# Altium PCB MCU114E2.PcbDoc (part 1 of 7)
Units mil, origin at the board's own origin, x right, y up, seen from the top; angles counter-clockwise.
Board outline 4153.94 x 2313.28 mil, 8 copper layers (Top Layer, GND 2, Signal Layer 3, Power 4, Power 5, Signal Layer 6, GND 7, Bottom), stack 61.2 mil thick; 444 components, 418 nets, 1811 pads, 981 vias.
Unrouted connection lines stored in the file: 3.
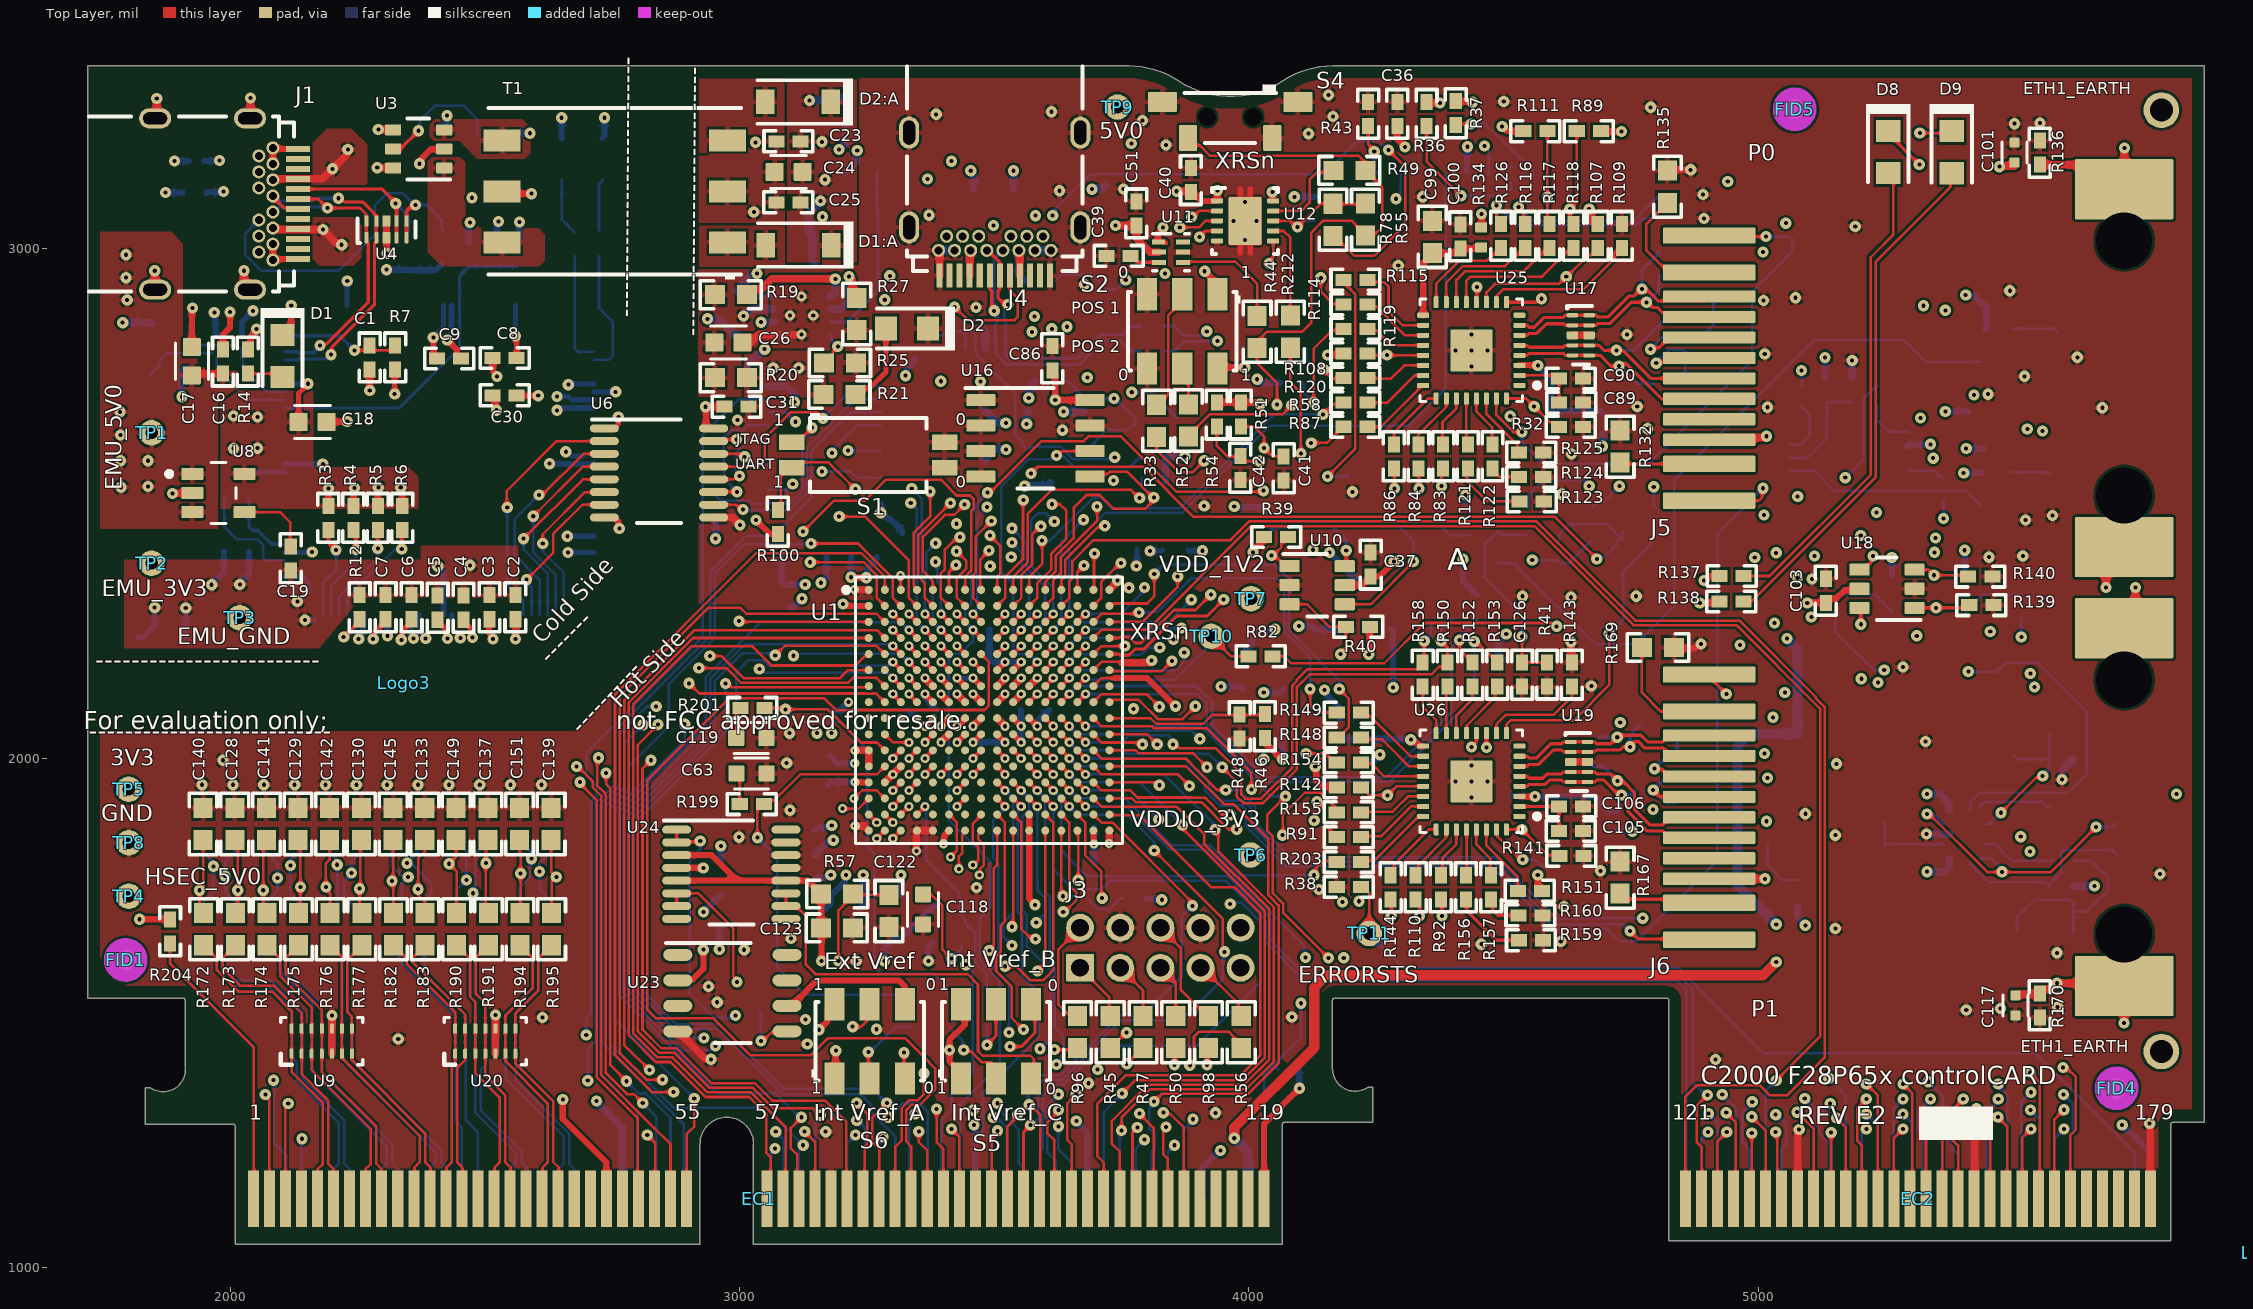
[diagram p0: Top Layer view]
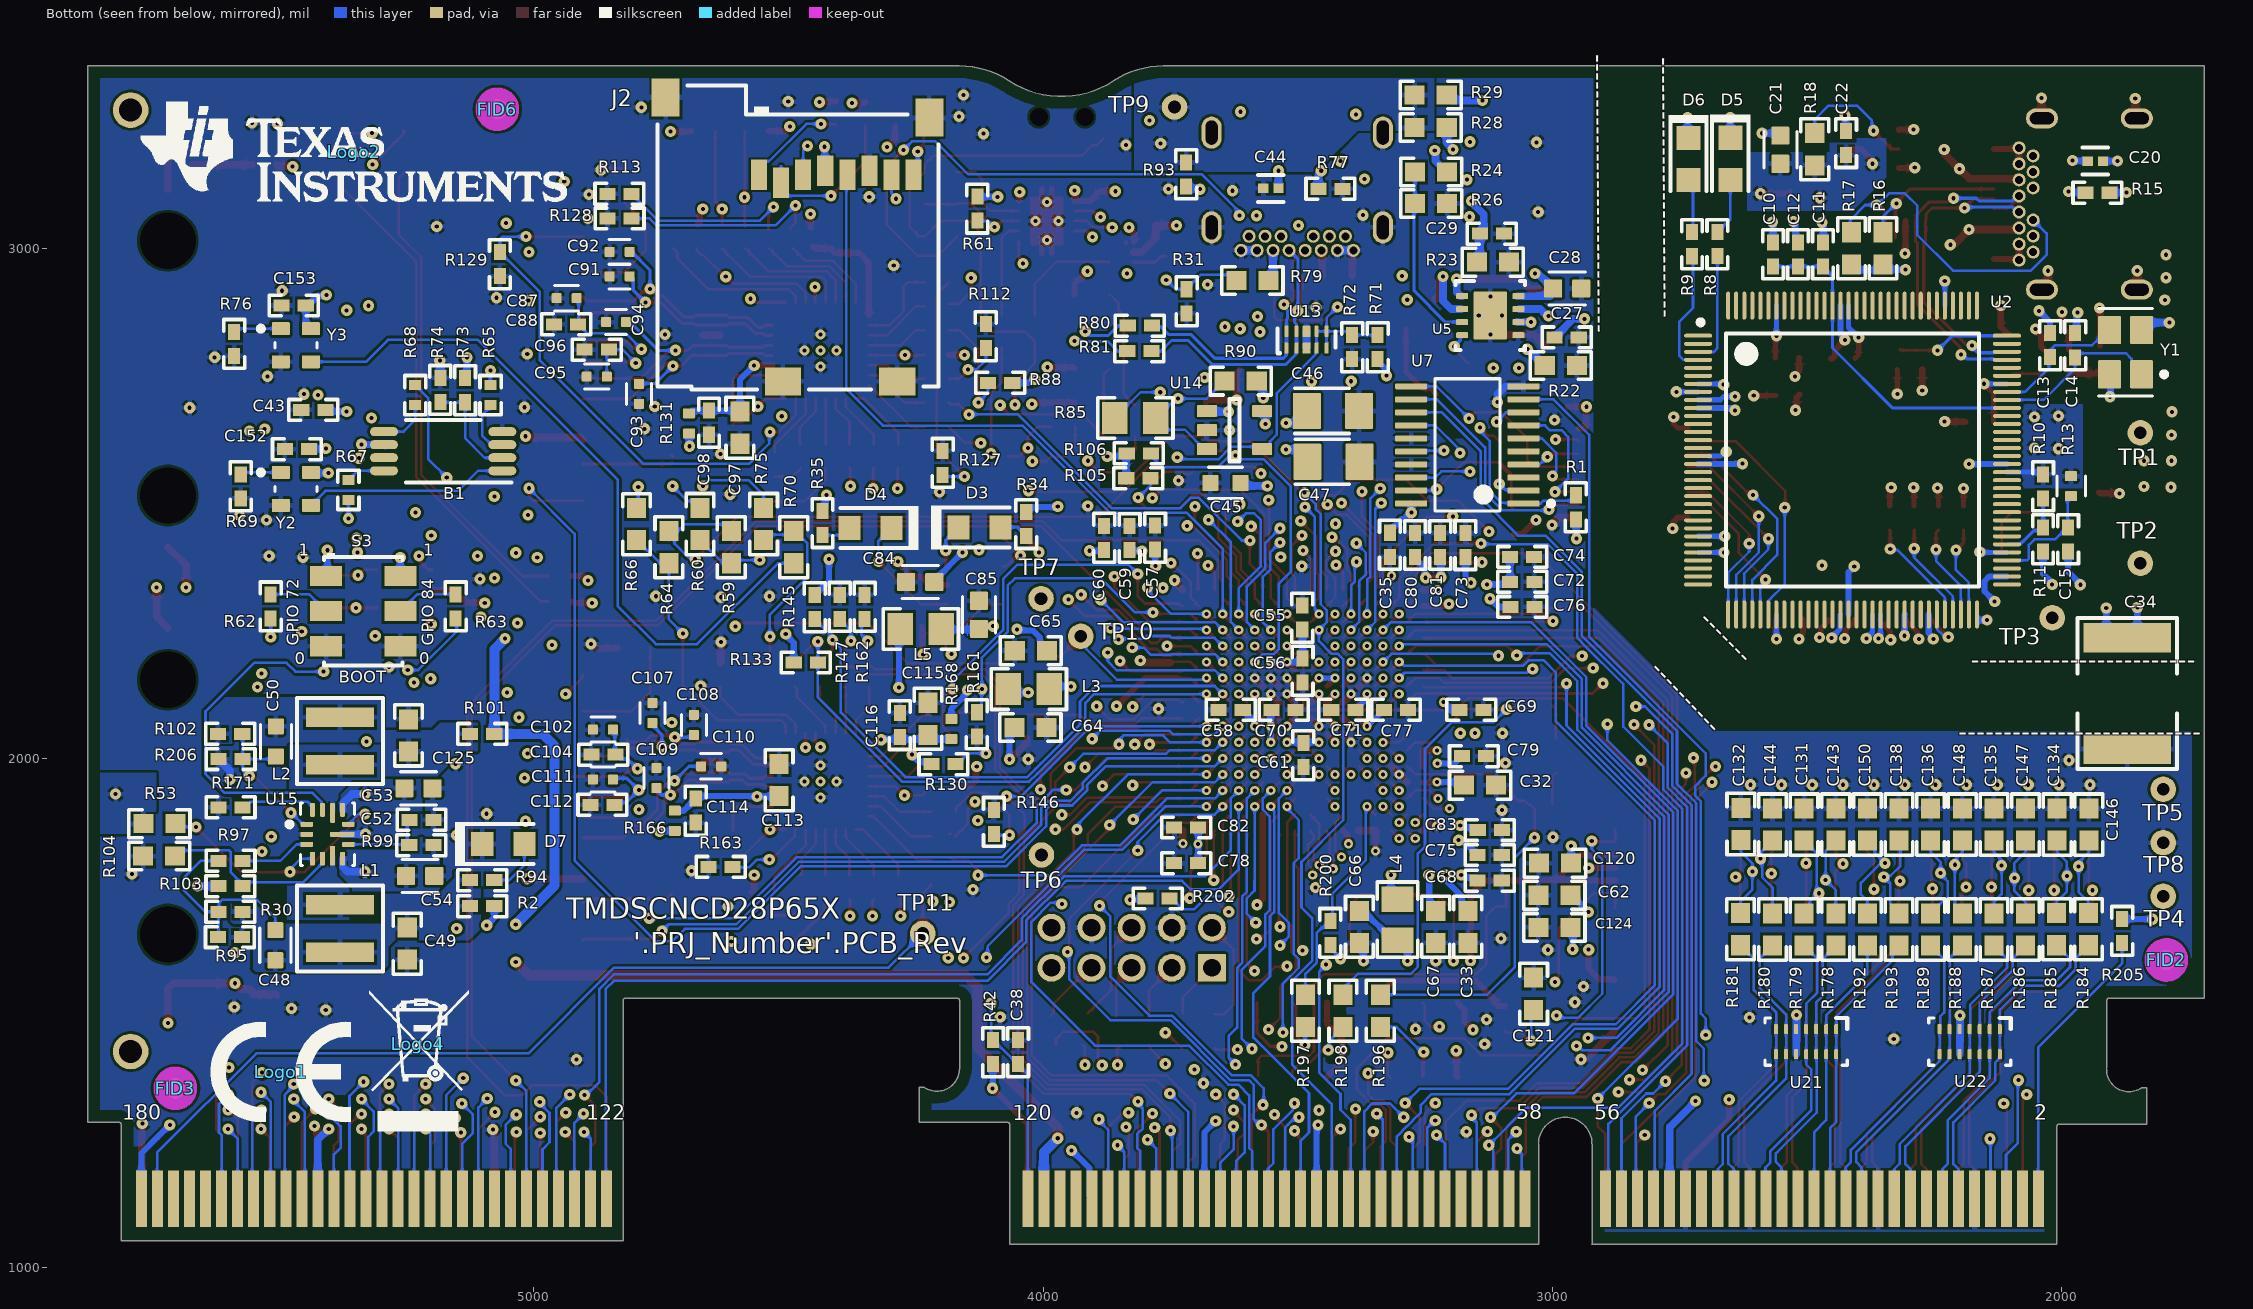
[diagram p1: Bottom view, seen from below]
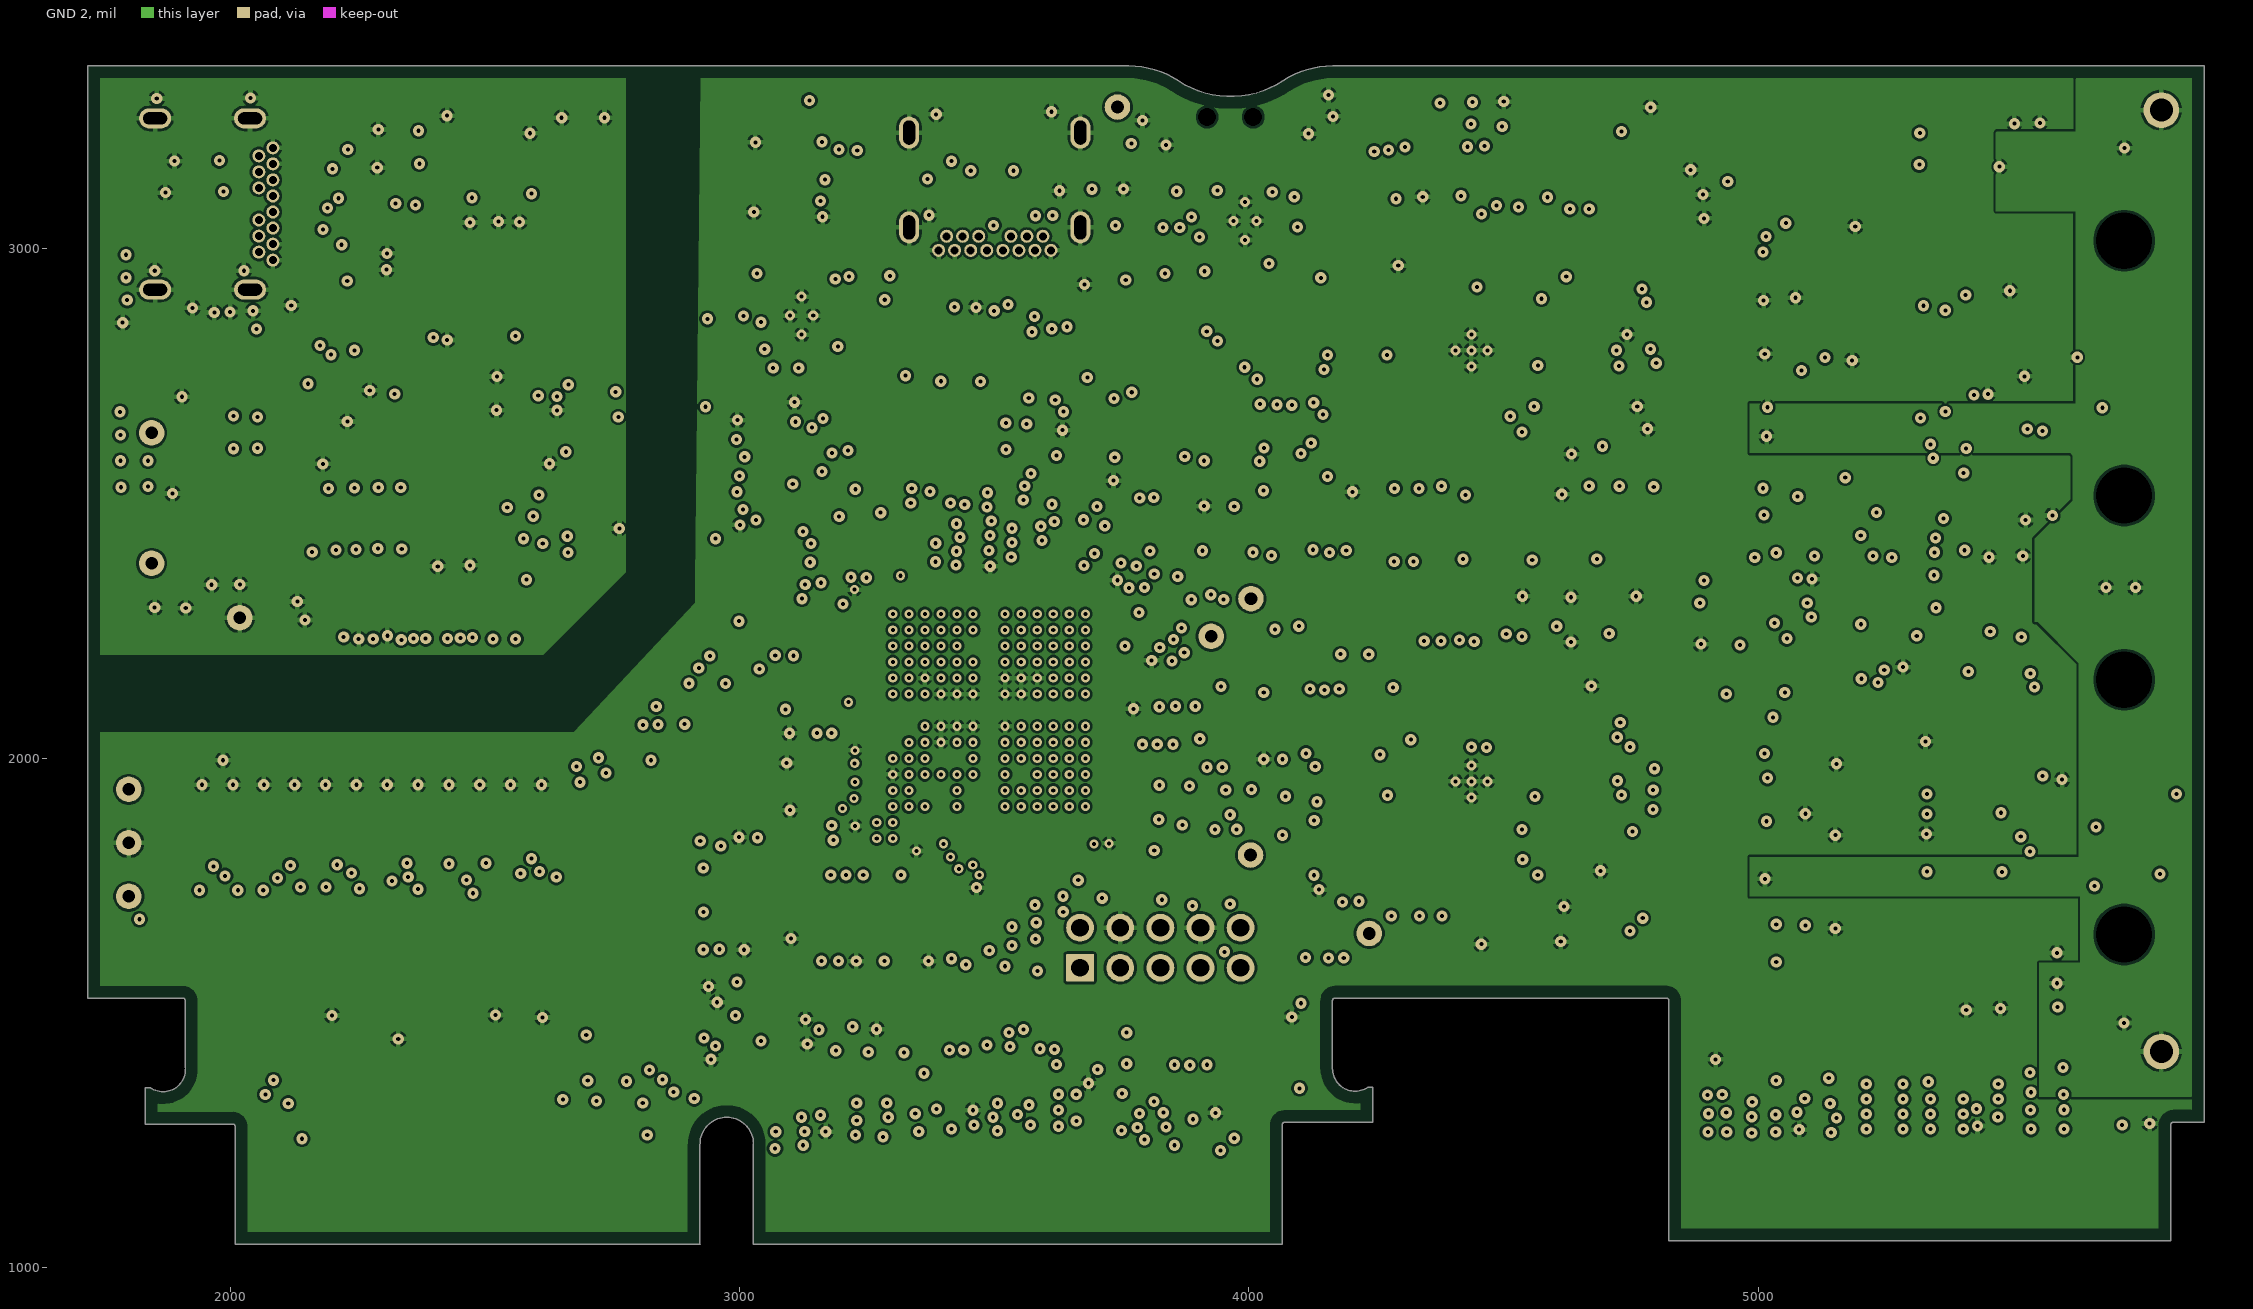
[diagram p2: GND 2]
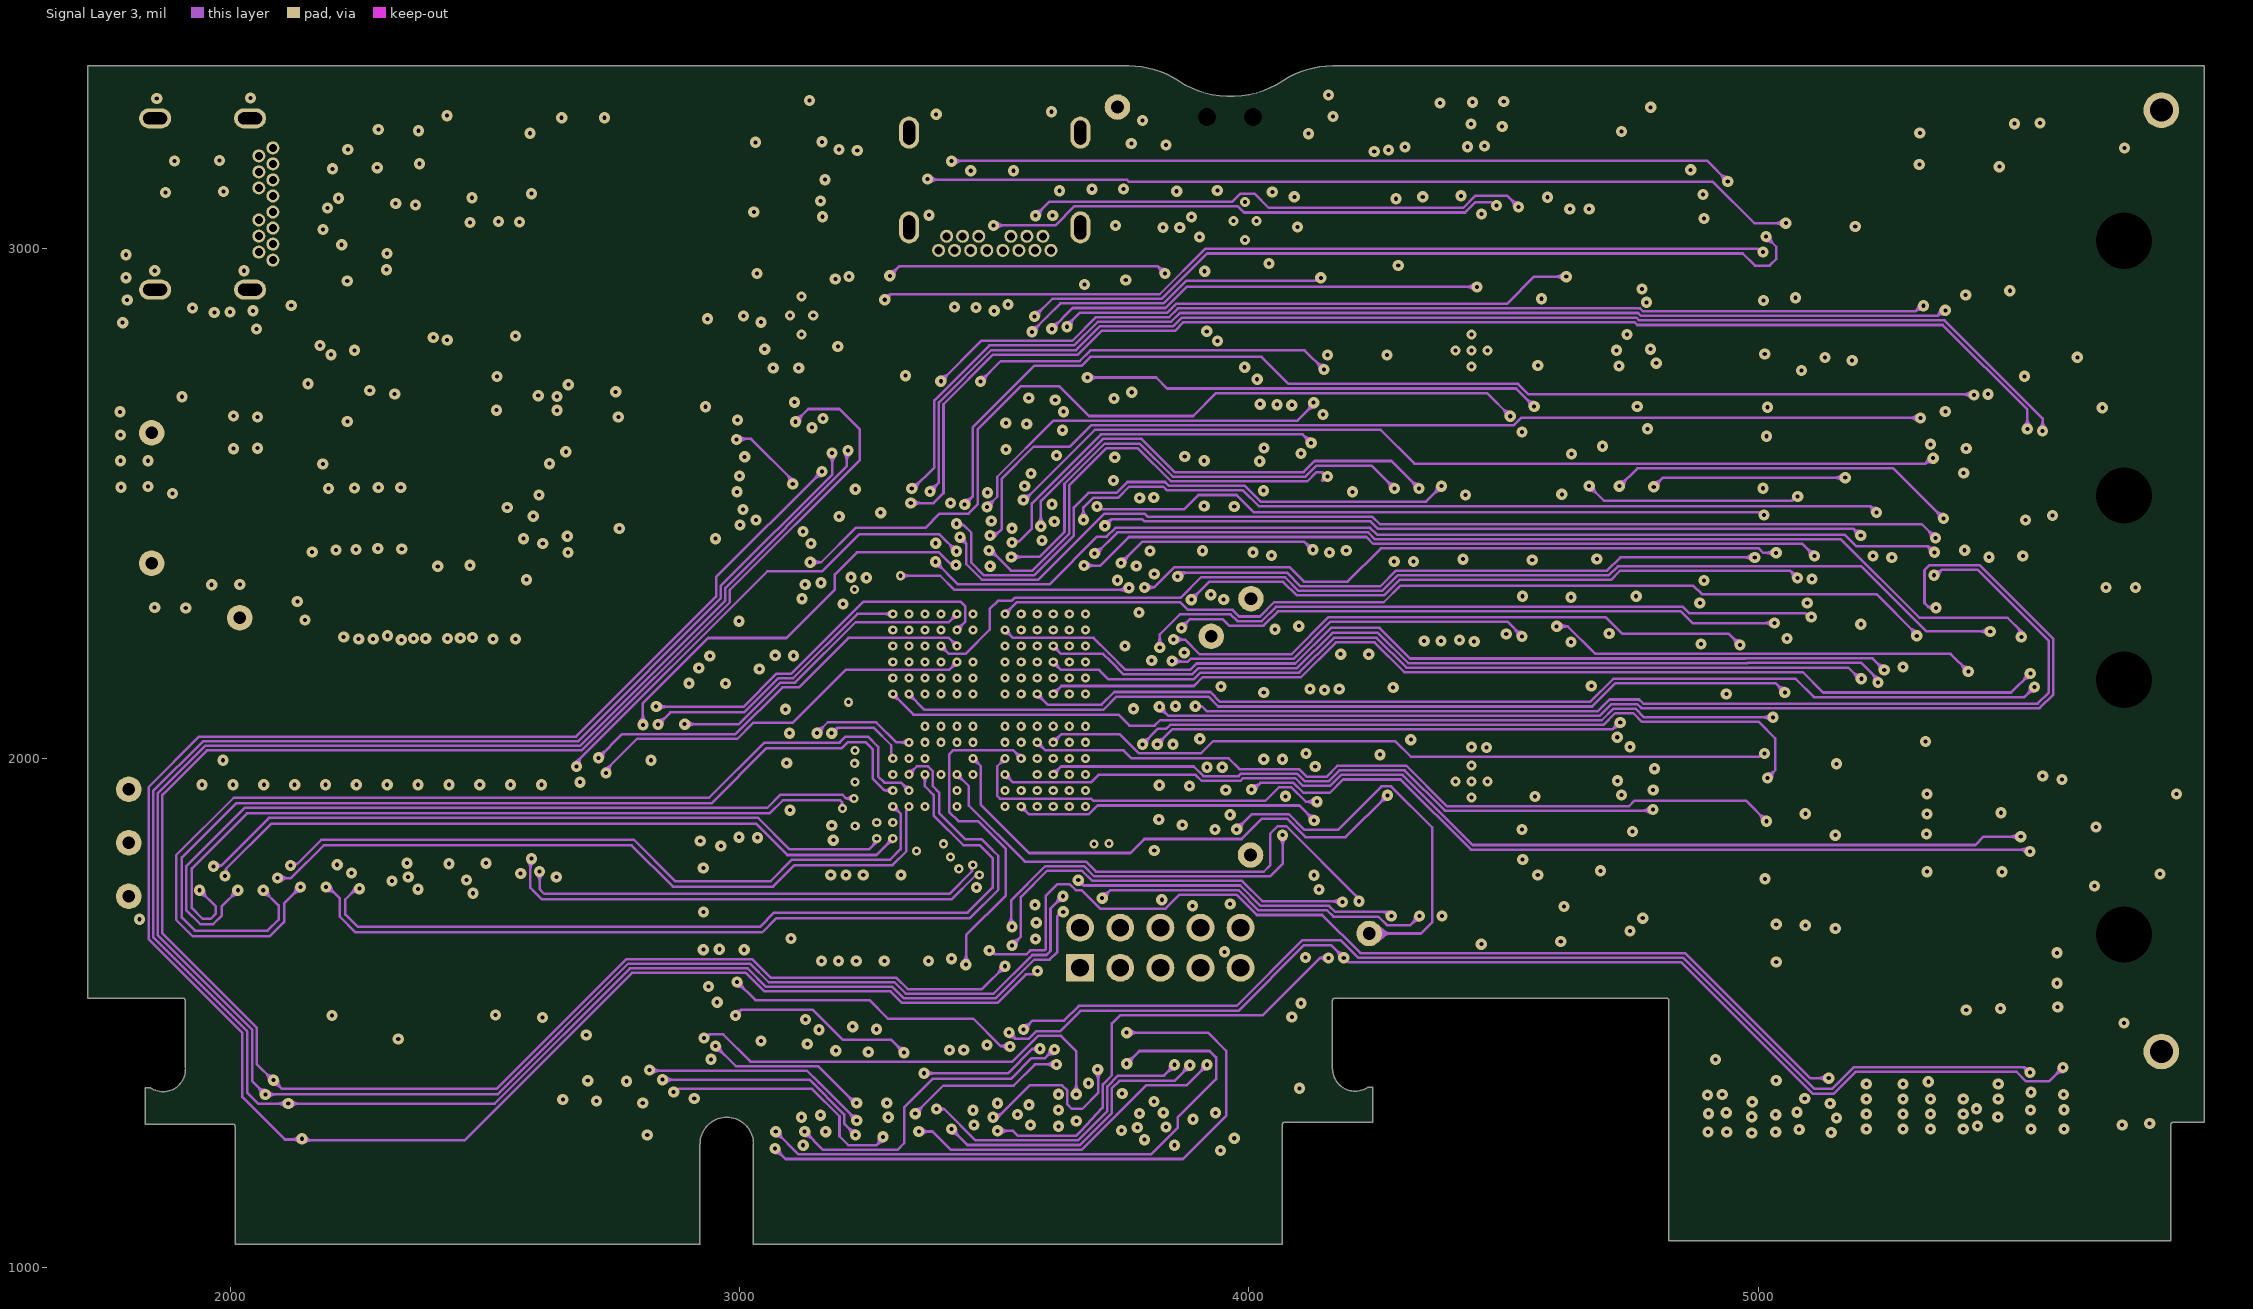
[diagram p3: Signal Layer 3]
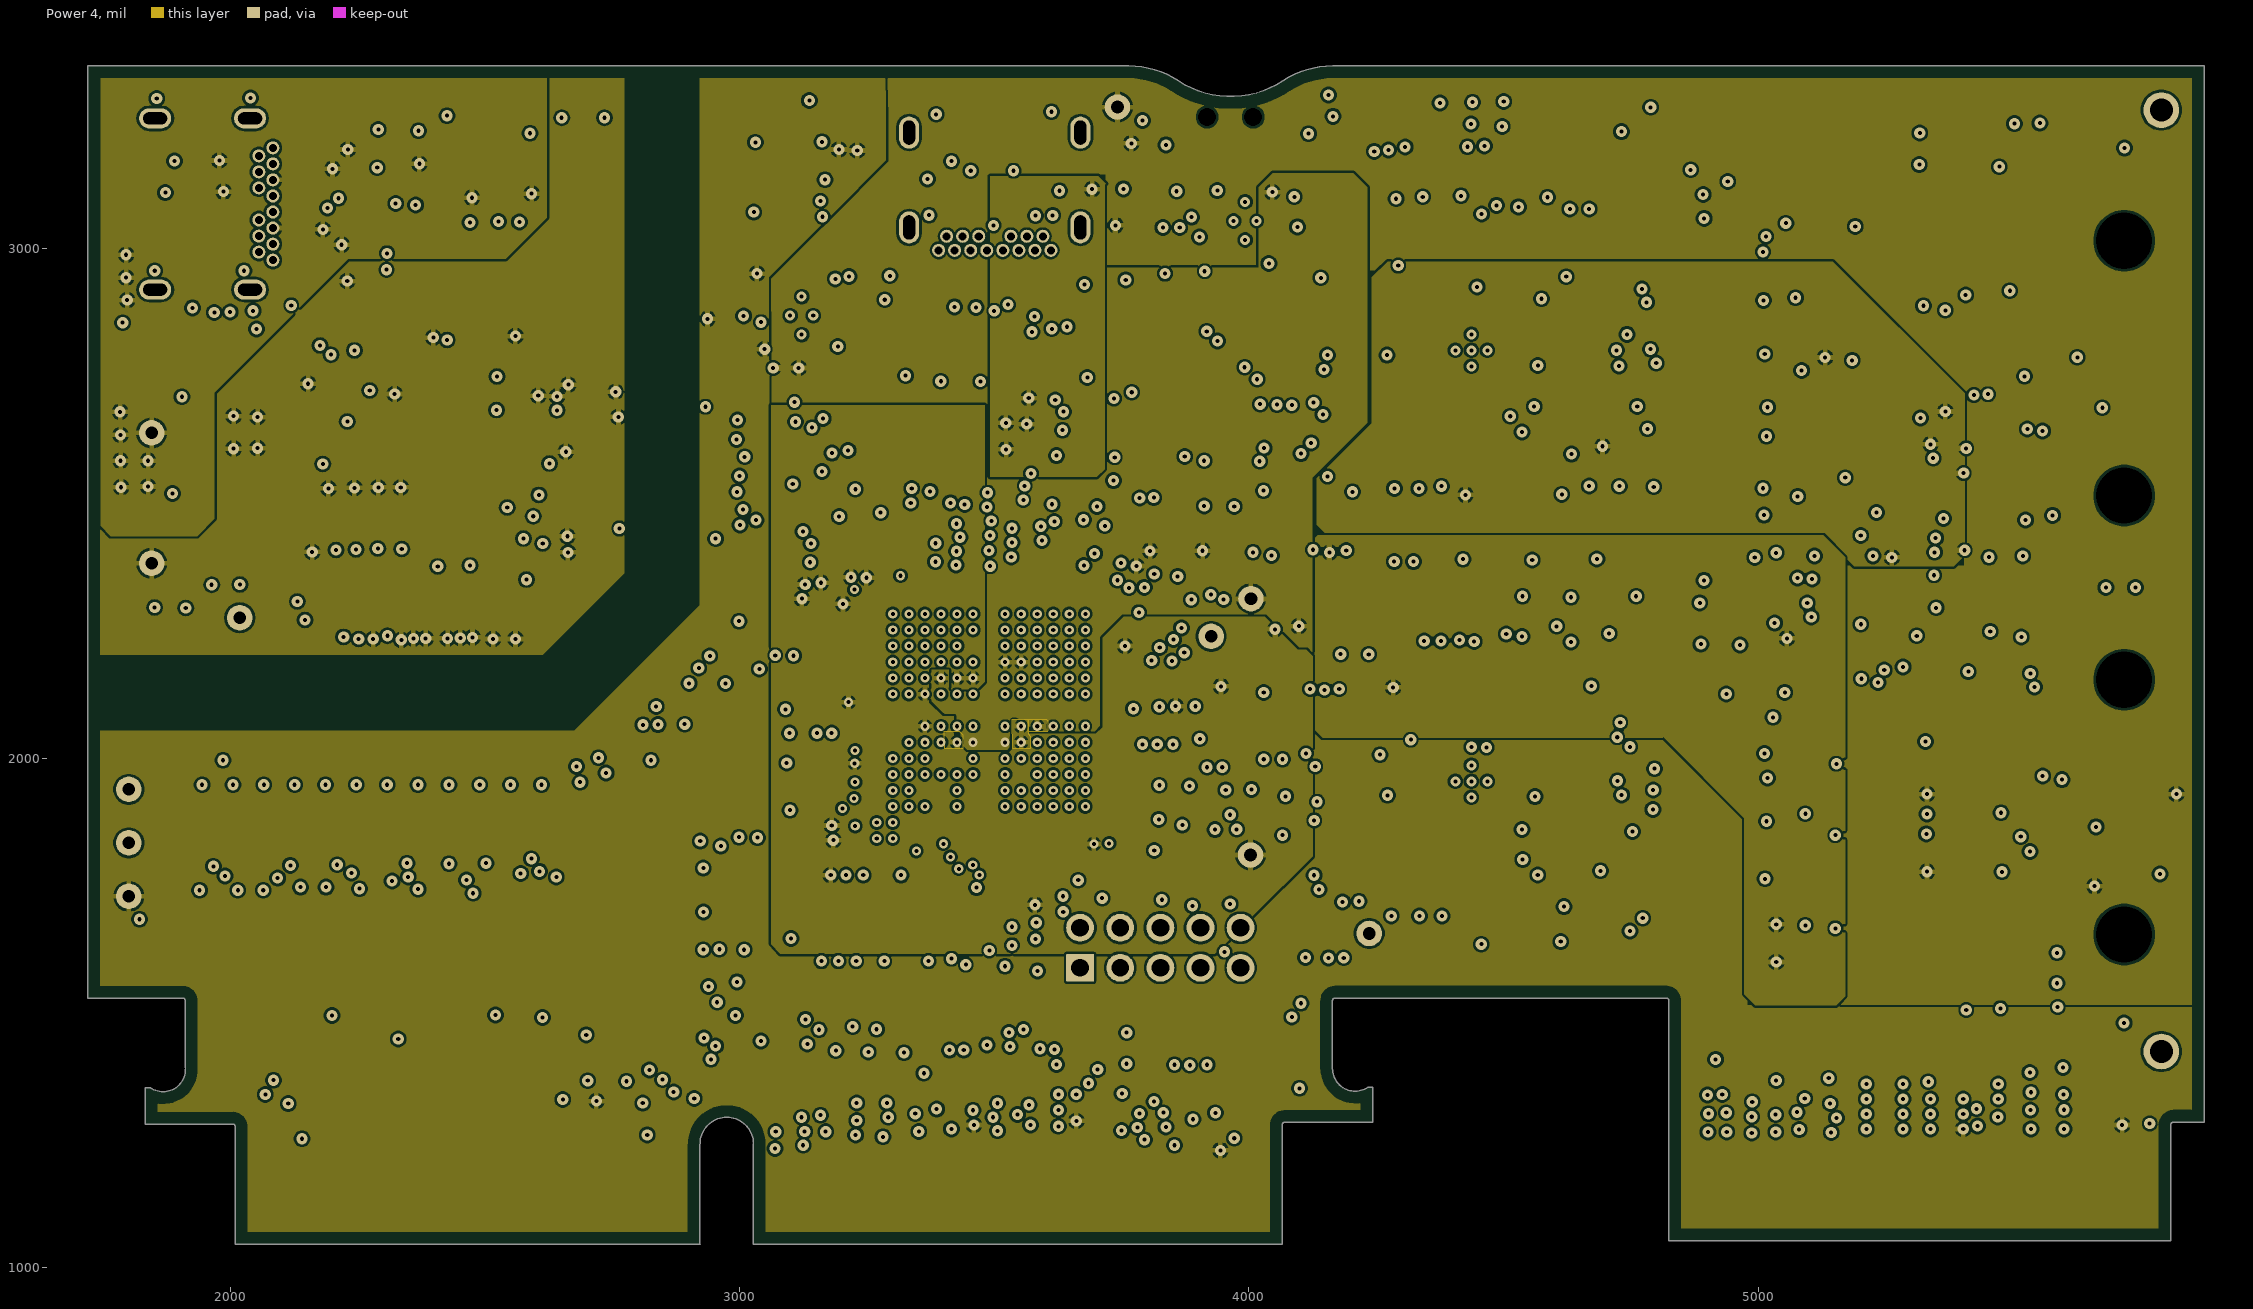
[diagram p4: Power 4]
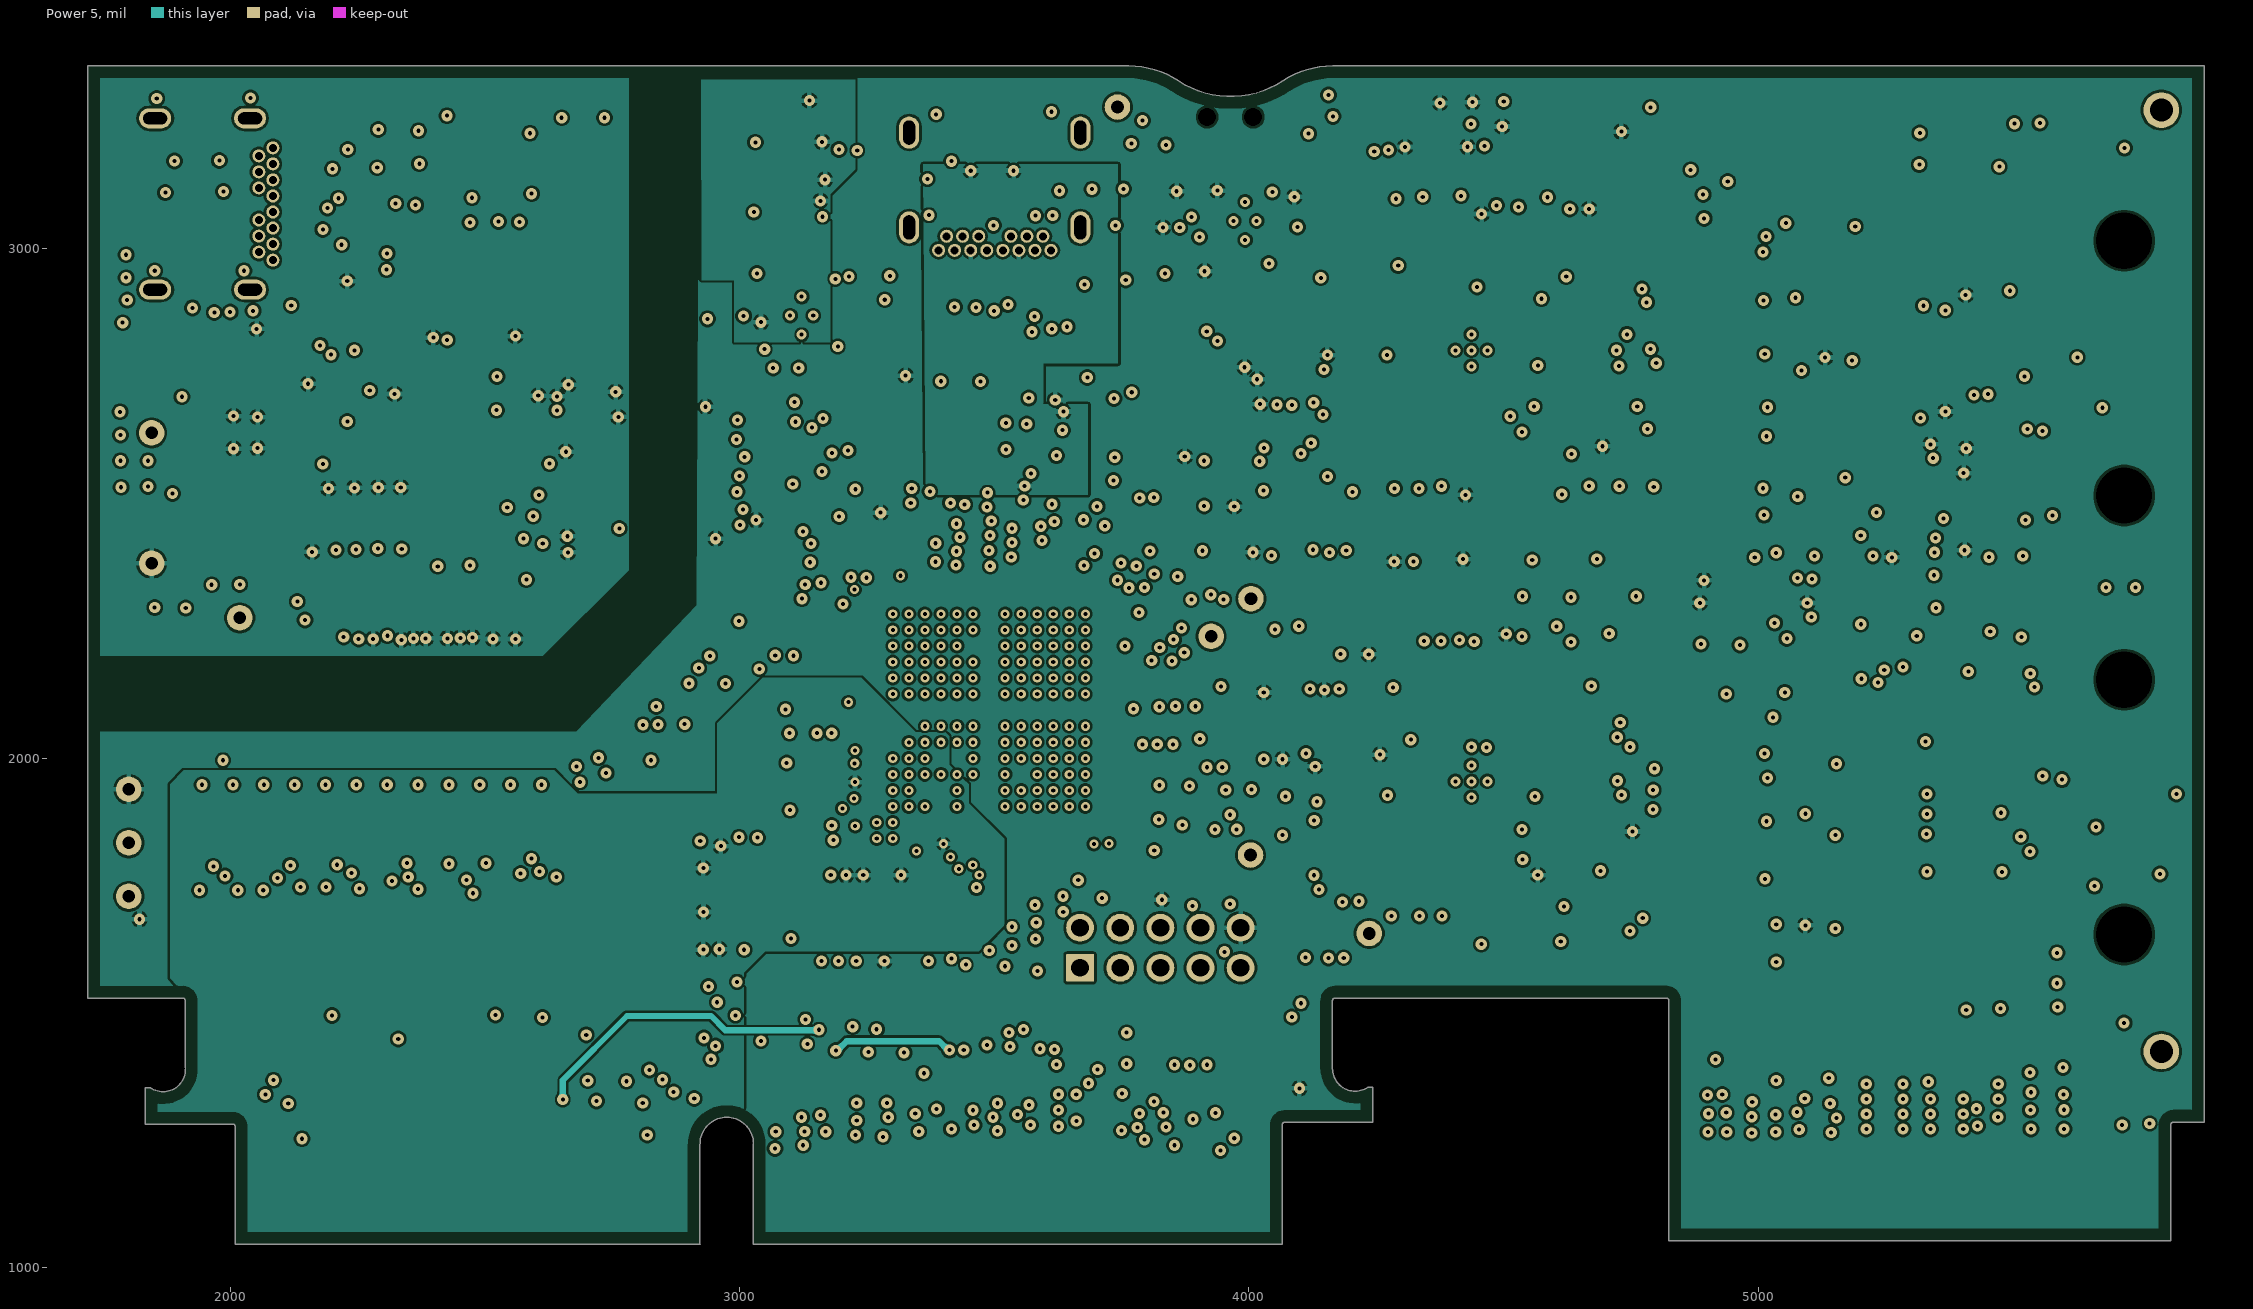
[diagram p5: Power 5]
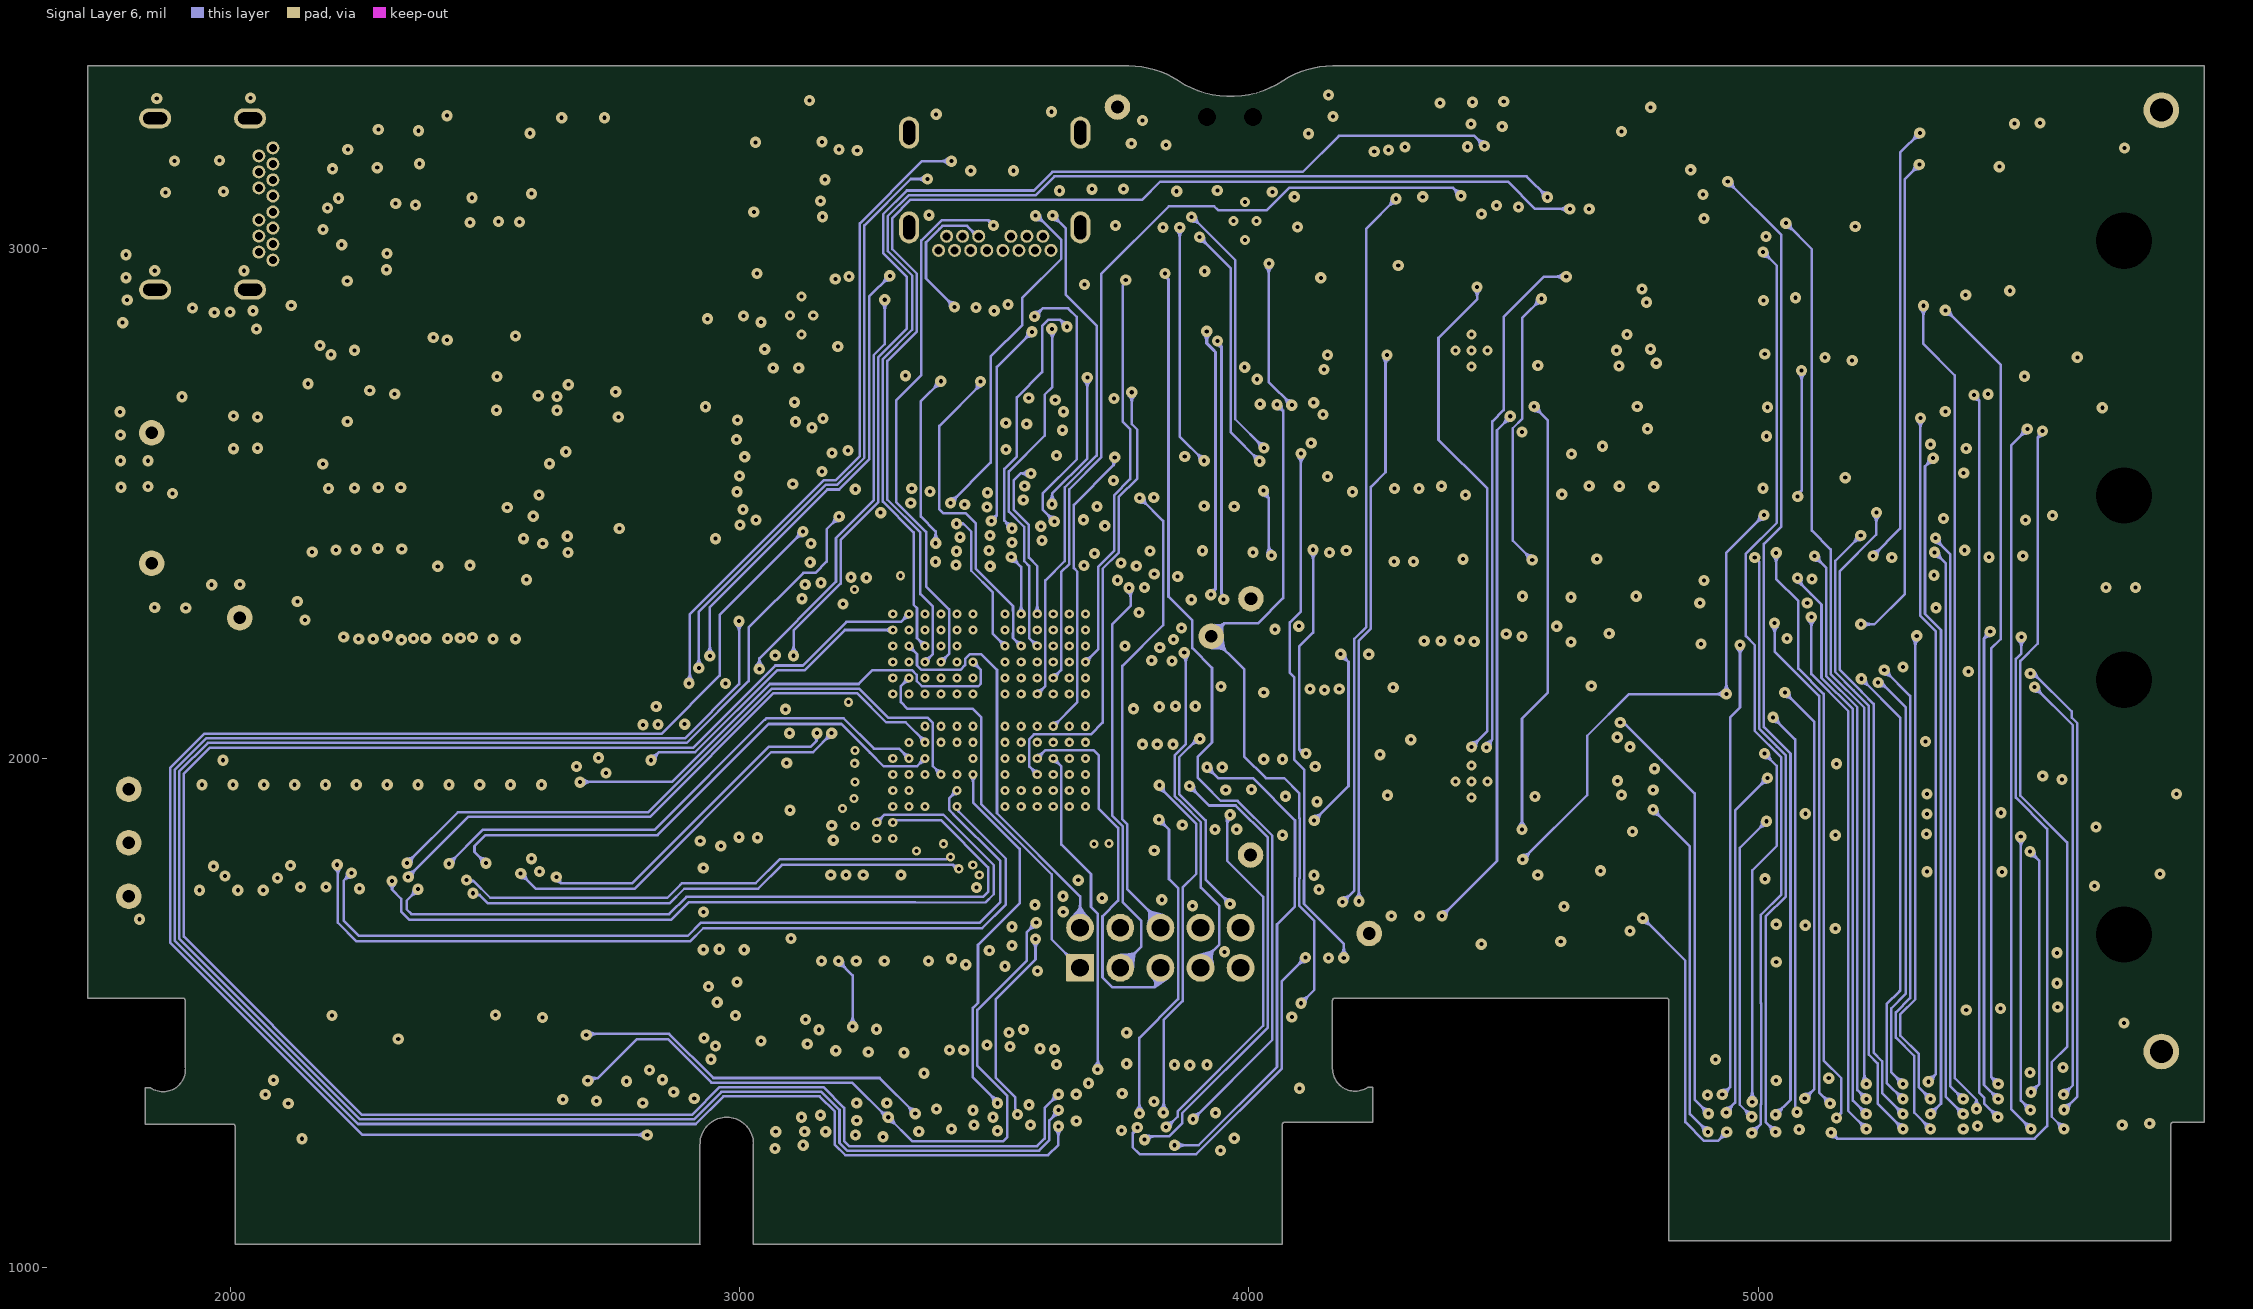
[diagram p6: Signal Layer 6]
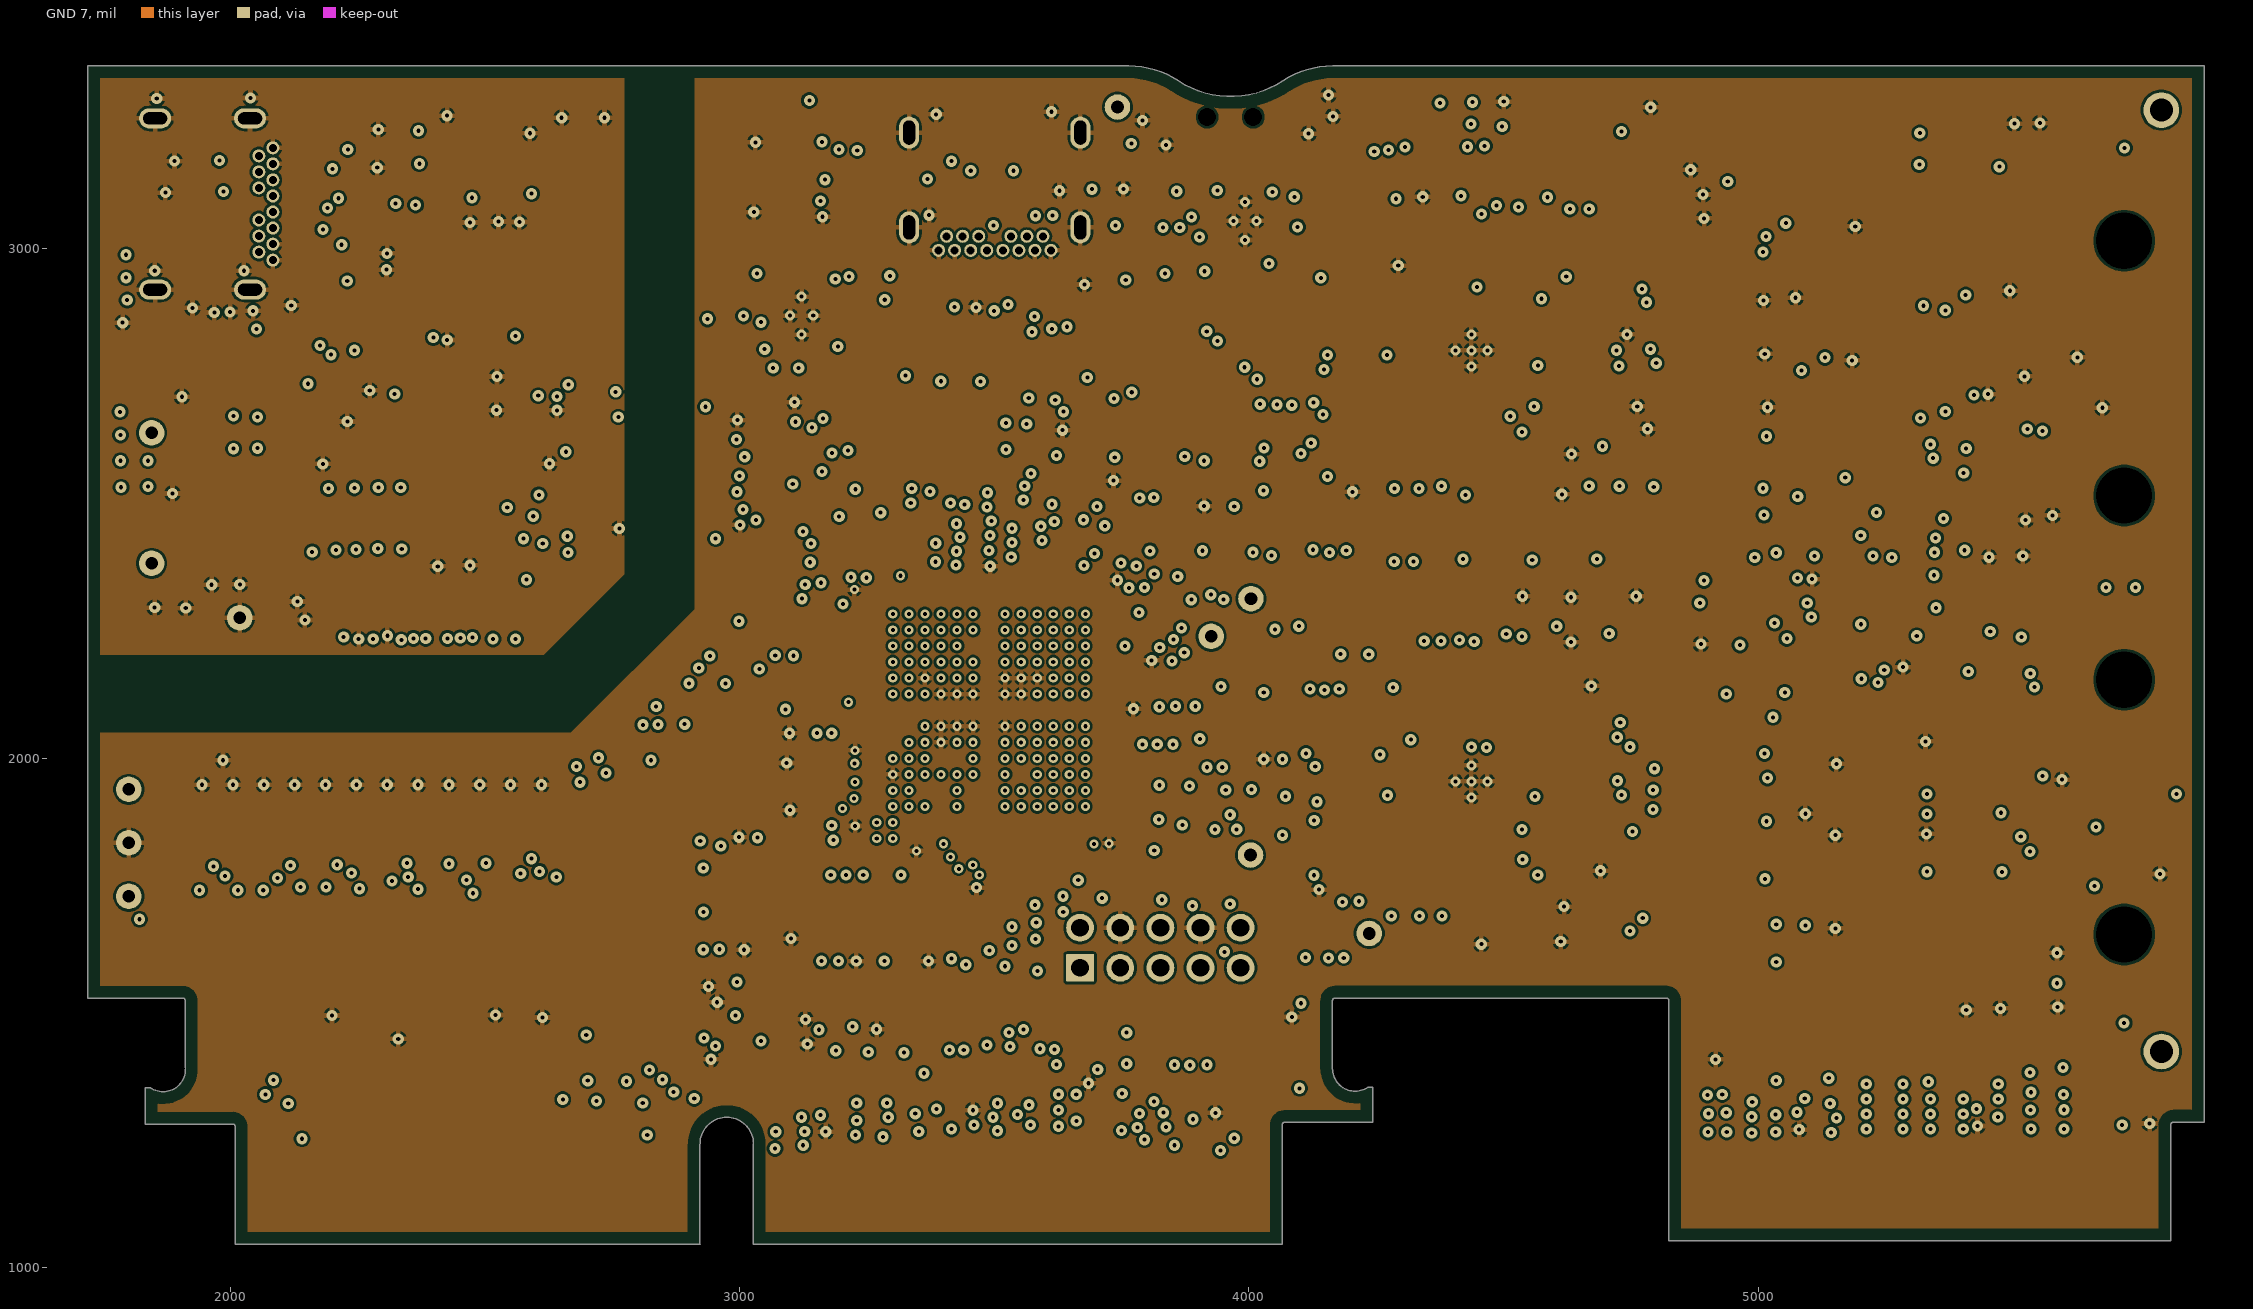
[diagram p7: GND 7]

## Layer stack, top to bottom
Top Solder: solder mask 0.5, Solder Resist, Dk 3.6
Top Layer: signal copper 1.4
Dielectric 1: prepreg 5, FR-4, Dk 3.7
GND 2: signal copper 1.4
Dielectric 2: core 10, FR-4, Dk 3.7
Signal Layer 3: signal copper 1.4
Dielectric 3: prepreg 5, FR-4, Dk 3.7
Power 4: signal copper 1.4
Dielectric 4: core 10, FR-4, Dk 3.7
Power 5: signal copper 1.4
Dielectric 5: prepreg 5, FR-4, Dk 3.7
Signal Layer 6: signal copper 1.4
Dielectric 6: core 10, FR-4, Dk 3.7
GND 7: signal copper 1.4
Dielectric 7: prepreg 5, FR-4, Dk 3.7
Bottom: signal copper 1.4
Bottom Solder: solder mask 0.5, Solder Resist, Dk 3.6

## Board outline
1833.82,1282.02 2005,1282.02 cw(c2005,1277) 2010.02,1277 2010.02,1045.98 2010.84,1046.05 2922.46,1046.05 2922.25,1047.48 2922.25,1241.96 2922.35,1242.97 cw(c2974.85,1242.55) 3027.35,1242.97 3027.35,1242.93 3027.35,1045.77 3027.41,1045.71 4065.16,1045.77 4065.09,1046.6 4065.09,1276.93 4065.38,1278.6 cw(c4070.11,1280.27) 4070.11,1285.28 4242.79,1285.28 4242.79,1354.25 4233.43,1354.25 cw(c4208.3,1390.39) 4164.35,1387.95 4163.79,1390.27 4163.79,1524.27 cw(c4168.8,1524.27) 4168.8,1529.28 4819.11,1529.28 cw(c4819.11,1524.27) 4824.13,1524.27 4824.13,1053.28 5809.38,1053.28 5809.38,1280.37 cw(c5814.39,1280.37) 5814.39,1285.38 5874.79,1285.38 5874.79,3358.99 4167,3358.99 4164,3358.99 ccw(c4164,3182.33) 4066.76,3329.81 cw(c3964,3485.67) 3861.24,3329.81 ccw(c3764,3182.33) 3764,3358.98 3763.85,3358.99 1720.85,3358.99 1720.85,1529.28 1906.8,1529.28 cw(c1906.8,1524.27) 1911.82,1524.27 1911.82,1393.48 1912.37,1389.36 cw(c1868.35,1389.36) 1843.18,1353.25 1833.82,1353.25

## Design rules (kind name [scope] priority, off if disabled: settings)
AcuteAngle [All] p1: minimum=4.50000000000000E+0001 checktracksonly=TRUE
AssemblyTestPointUsage [All] p1: valid=2
BoardOutlineClearance "Edge exception" [OnCopper and Not InComponentClass('Logo') and not InComponentClass('FiducialMark') and not InRegion(1000,500,4000,800) and not InPoly and ((Name = 'EC2') or (Name = 'EC1'))] p1: gap=0 ignorepadtopadclearanceinfootprint=FALSE
BoardOutlineClearance [All] p2: gap=24 ignorepadtopadclearanceinfootprint=FALSE except(0: Text-OutlineEdge; 15: Arc-OutlineEdge Track-OutlineEdge SMDPad-OutlineEdge Fill-OutlineEdge)
BoardOutlineClearance BoardOutlineClearance_MountingHoles [OnCopper and InComponentClass('Mounting Holes')] p3: gap=40 ignorepadtopadclearanceinfootprint=FALSE
BoardOutlineClearance BoardOutlineClearance_Poly [OnCopper and IsPoly] p4: gap=25 ignorepadtopadclearanceinfootprint=FALSE
Clearance "Clearance_RJ45 pad" [InComponent('J5') OR InComponent('J6')] p1: gap=5 ignorepadtopadclearanceinfootprint=TRUE except(0: SMDPad-THPad)
Clearance Clearance_Keepouts [((IsTrack Or IsArc) And Not InPoly) And IsFree and IsKeepOut vs ((IsTrack Or IsArc) And Not InPoly) And IsFree and IsKeepOut] p2: gap=5 ignorepadtopadclearanceinfootprint=FALSE
Clearance Clearance_Poly [InPolygon] p3: gap=5 ignorepadtopadclearanceinfootprint=FALSE
Clearance Clearance_FiducialMark [IsKeepOut and InComponentClass('FiducialMark') vs IsPad and InComponentClass('FiducialMark')] p4: gap=0 ignorepadtopadclearanceinfootprint=FALSE
Clearance [All] p5: gap=5 ignorepadtopadclearanceinfootprint=FALSE except(4: Arc-Arc Arc-Track Arc-Via Track-Track Track-Via)
ComponentClearance ComponentClearance_TI_LOGO [InComponentClass('Logo')] p1: gap=0 collisioncheckmode=3 verticalgap=0 showdistances=FALSE
ComponentClearance ComponentClearance_MountingHoles_FiducialMarks [InComponentClass('Mounting Holes') vs InComponentClass('FiducialMark')] p2: gap=10 collisioncheckmode=3 verticalgap=10 showdistances=FALSE
ComponentClearance ComponentClearance_Shunt [InComponentClass('Header') vs InComponentClass('Shunt')] p3: gap=0 collisioncheckmode=3 verticalgap=0 showdistances=FALSE
ComponentClearance ComponentClearance_Logo [InComponentClass('Logo')] p4: gap=10 collisioncheckmode=3 verticalgap=10 showdistances=FALSE
ComponentClearance ComponentClearance_ScrewToNut [(HasFootprint('NY PMS 440 0025 PH')) vs (HasFootprint('Keystone_1902C'))] p5: gap=5 collisioncheckmode=3 verticalgap=10 showdistances=FALSE
ComponentClearance ComponentClearance_MountingHoles [InComponentClass('Mounting Holes')] p6: gap=250 collisioncheckmode=3 verticalgap=100000 showdistances=FALSE
ComponentClearance ComponentClearance_SmallPassives [HasFootprint('0201*') or HasFootprint('0402*') or HasFootprint('0508') or HasFootprint('0603*') or HasFootprint('0612') or HasFootprint('0805*') or HasFootprint('0815*') or HasFootprint('0830*') or HasFootprint('1206*') or HasFootprint('1210*') or HasFootprint('1808*') or HasFootprint('1812*') or HasFootprint('1825*') or HasFootprint('2010*') or HasFootprint('2220*') or HasFootprint('2225*') or HasFootprint('2512*') or HasFootprint('2728*') or HasFootprint('3518*') vs HasFootprint('0201*') or HasFootprint('0402*') or HasFootprint('0508') or HasFootprint('0603*') or HasFootprint('0612') or HasFootprint('0805*') or HasFootprint('0815*') or HasFootprint('0830*') or HasFootprint('1206*') or HasFootprint('1210*') or HasFootprint('1808*') or HasFootprint('1812*') or HasFootprint('1825*') or HasFootprint('2010*') or HasFootprint('2220*') or HasFootprint('2225*') or HasFootprint('2512*') or HasFootprint('2728*') or HasFootprint('3518*')] p7: gap=14.96 collisioncheckmode=3 verticalgap=10 showdistances=FALSE
ComponentClearance ComponentClearance_THtoSMT [IsThruComponent vs IsSMTComponent] p8: gap=30 collisioncheckmode=3 verticalgap=30 showdistances=FALSE
ComponentClearance "ComponentClearance_TP to TP" [(INComponent('TP1:A') or InComponent('TP2:A') or InComponent('TP3:A')or InComponent('TP7') or InComponent('TP2') or InComponent('TP3') or InComponent('TP10')) vs (INComponent('TP1:A') or InComponent('TP2:A') or InComponent('TP3:A')or InComponent('TP7') or InComponent('TP2') or InComponent('TP3') or InComponent('TP10'))] p9: gap=20 collisioncheckmode=3 verticalgap=20 showdistances=FALSE
ComponentClearance ComponentClearance_THtoTH [IsThruComponent vs IsThruComponent] p10: gap=30 collisioncheckmode=3 verticalgap=30 showdistances=FALSE
ComponentClearance [All] p11: gap=10 collisioncheckmode=3 verticalgap=10 showdistances=FALSE
DiffPairsRouting [All] p1: maxlimit=10 minlimit=6 mostfreqgap=6 toplayer_minwidth=4.9 toplayer_maxwidth=6.2 toplayer_prefwidth=4.9 midlayer1_minwidth=4.9 midlayer1_maxwidth=6.2 midlayer1_prefwidth=4.9 midlayer2_minwidth=4.9 midlayer2_maxwidth=15 midlayer2_prefwidth=4.9 midlayer3_minwidth=4.9 midlayer3_maxwidth=15 midlayer3_prefwidth=4.9 midlayer4_minwidth=4.9 midlayer4_maxwidth=6.2 midlayer4_prefwidth=4.9 midlayer5_minwidth=4.9 midlayer5_maxwidth=15 midlayer5_prefwidth=4.9 midlayer6_minwidth=4.9 midlayer6_maxwidth=15 midlayer6_prefwidth=4.9 bottomlayer_minwidth=4.9 bottomlayer_maxwidth=6.2 bottomlayer_prefwidth=4.9 maxuncoupledlength=500
DiffPairsRouting DiffPairsRouting_90 [InDifferentialPairClass('All Differential Pairs')] p2: maxlimit=6 minlimit=5 mostfreqgap=6 toplayer_minwidth=6 toplayer_maxwidth=6.1 toplayer_prefwidth=6.1 midlayer1_mingap=6 midlayer1_minwidth=6 midlayer1_maxwidth=6.1 midlayer1_prefwidth=6.1 midlayer2_mingap=6 midlayer2_minwidth=6 midlayer2_maxwidth=6.1 midlayer2_prefwidth=6.1 midlayer3_mingap=6 midlayer3_minwidth=6 midlayer3_maxwidth=6.1 midlayer3_prefwidth=6.1 midlayer4_mingap=6 midlayer4_minwidth=6 midlayer4_maxwidth=6.1 midlayer4_prefwidth=6.1 midlayer5_mingap=6 midlayer5_minwidth=6 midlayer5_maxwidth=6.1 midlayer5_prefwidth=6.1 midlayer6_mingap=6 midlayer6_minwidth=6 midlayer6_maxwidth=6.1 midlayer6_prefwidth=6.1 bottomlayer_minwidth=6 bottomlayer_maxwidth=6.1 bottomlayer_prefwidth=6.1 maxuncoupledlength=1000
FabricationTestPointUsage TestPointUsage [All] p1: valid=2 allowmultiple=FALSE
FabricationTestpoint Testpoint [All] p1: side=3 testpointundercomponent=TRUE minsize=40 maxsize=100 preferedsize=60 minholesize=0 maxholesize=40 preferedholesize=32 testpointgrid=1 allowsidetop=TRUE allowsidebottom=TRUE usegrid=TRUE gridtolerance=0.01
FanoutControl Fanout_LCC [IsLCC] p1: bgadir=Out bgaviamode=Centered fanoutstyle=Auto fanoutdirection=Alternating viagrid=1 // Fanout_LCC (Default Rule)
FanoutControl Fanout_BGA [IsBGA] p2: bgadir=Out bgaviamode=Centered fanoutstyle=Auto fanoutdirection=Alternating viagrid=1 // Fanout_BGA (Default Rule)
FanoutControl Fanout_Default [All] p4: bgadir=Out bgaviamode=Centered fanoutstyle=Auto fanoutdirection=Alternating viagrid=1 // Fanout_Default (Default Rule)
FanoutControl Fanout_Small [(CompPinCount < 5)] p5: bgadir=Out bgaviamode=Centered fanoutstyle=Auto fanoutdirection=OutThenIn viagrid=1 // Fanout_Small (Default Rule)
HoleSize [All] p1: absolutevalues=TRUE maxlimit=251 minlimit=7.87 maxpercent=80.000 minpercent=20.000
MinimumAnnularRing MinimumAnnularRing_ThermalPadVias [IsVia and InAnyComponent] p1: minimumring=4.9
MinimumAnnularRing [All] p2: minimumring=4.9
MinimumSolderMaskSliver MinimumSolderMaskSliver_Logo [InComponentClass('Logo') vs InComponentClass('Logo')] p1: minsoldermaskwidth=0.7
MinimumSolderMaskSliver [All] p2: minsoldermaskwidth=3.94
PlaneClearance PlaneClearance_1 [All] p1: clearance=10
PlaneClearance PlaneClearance_via [IsVia] p2: clearance=10
PlaneConnect [All] p1: planeconnectstyle=Relief reliefexpansion=10 reliefentries=4 reliefconductorwidth=10 reliefairgap=10
PolygonConnect 'POWER_4_VDDIO_3V3_P226' [Name = 'POWER_4_VDD_1V2_P187'] p1: connectstyle=Direct reliefconductorwidth=10 reliefentries=4 polygonreliefangle="90 Angle" airgapwidth=10
PolygonConnect PolygonConnect_1 [All] p2: connectstyle=Relief reliefconductorwidth=10 reliefentries=4 polygonreliefangle="90 Angle" airgapwidth=5
PolygonConnect PolygonConnect_via [isvia] p3: connectstyle=Relief reliefconductorwidth=10 reliefentries=4 polygonreliefangle="90 Angle" airgapwidth=5
RoutingVias [All] p1: holewidth=8 width=22 viastyle="Through Hole" minholewidth=7.87 minwidth=18 maxholewidth=8 maxwidth=22
ShortCircuit ShortCircuit_RJ45pad [InComponent('J5') And IsThruPin Or InComponent('J6') And IsThruPin] p1: allowed=TRUE // to prevent short ckt between deisngator ALIGN1 and ETH1_EARTH PAD
ShortCircuit [All] p2: allowed=FALSE
SilkToBoardRegionClearance [Not ((IsComment or IsDesignator) And (Hide <> 'False')) and not InRegion(1000,500,4000,800)] p1:
SilkToSilkClearance SilkToSilkClearance_Pb-FreeLogo [(HasFootprint('Pb-Free_Overlay_Medium') OR HasFootprint('Pb-Free_Overlay_Small')) vs (HasFootprint('Pb-Free_Overlay_Medium') OR HasFootprint('Pb-Free_Overlay_Small'))] p1: silktosilkclearance=0
SilkToSilkClearance [All] p2: silktosilkclearance=3
SilkToSolderMaskClearance SilkToComponentPadClearance [(IsPad or IsFill or IsRegion) and InAnycomponent] p1: minsilkscreentomaskgap=3 clearancetoexposedcopper=TRUE
SilkToSolderMaskClearance "Silk to Solder Mask Opening" [All] p2: minsilkscreentomaskgap=3 clearancetoexposedcopper=FALSE
SolderMaskExpansion [All] p1: expansion=1.97 istentingtop=FALSE
UnRoutedNet [All] p1: checkbadconnections=TRUE
Width USB_Width [InNetClass('USB')] p1: maxlimit=6.25 minlimit=6.1 preferedwidth=6.25 checkconnectedcopper=TRUE
Width [All] p2: maxlimit=20 minlimit=5 preferedwidth=5 checkconnectedcopper=TRUE
12 further rules are at their usual default settings.

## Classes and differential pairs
component class MCU114E2_EVM_Hardware: !PCB1 FID1 FID2 FID3 FID4 FID5 FID6 Logo1 Logo2 Logo3 Logo4 ZZ1 ZZ2 ZZ3 ZZ4
component class Logo: Logo2
component class FiducialMark: FID1 FID2 FID3 FID4 FID5 FID6
component class AssemblyNote: ZZ1 ZZ2 ZZ3 ZZ4
component class MCU114E2_XDS110_USB_Power: C16 C17 C18 C19 C20 C21 C22 C23 C24 C25 C26 C27 C28 C29 D1 D1:A D2 D2:A J1 R14 R15 R16 R17 R18 R19 R20 R21 R22 R23 R24 R25 R26 R27 R28 R29 T1 TP1 TP2 TP3 U3 U4 U5 U8
component class MCU114E2_XDS110_MCU: C1 C2 C3 C4 C5 C6 C7 C8 C9 C10 C11 C12 C13 C14 C15 D5 D6 R3 R4 R5 R6 R7 R8 R9 R10 R11 R12 R13 U2 Y1
component class MCU114E2_USB: C44 C45 C46 C47 J4 R31 R71 R72 R77 R79 R80 R81 R85 R90 U13 U14
component class MCU114E2_Support: B1 C36 C37 C38 C39 C40 C41 C42 C43 C51 C126 C152 C153 D3 D4 J2 J3 R33 R34 R35 R36 R37 R38 R39 R40 R41 R42 R43 R44 R45 R46 R47 R48 R49 R50 R51 R52 R54 R55 R56 R59 R60 R61 R62 R63 R64 R65 R66 R67 R68 R69 R70 R73 R74 R75 R76 R78 R96 R98 R202 R212 S2 S3 S4 TP10 TP11 U10 U11 U12 Y2 Y3
component class MCU114E2_Power: C32 C33 C48 C49 C50 C52 C53 C54 C55 C56 C57 C58 C59 C60 C61 C64 C65 C66 C67 C68 C69 C70 C71 C72 C73 C74 C75 C76 C77 C78 C79 C80 C81 C82 C83 C84 C85 C125 D7 L1 L2 L3 L4 L5 R2 R30 R53 R82 R93 R94 R95 R97 R99 R101 R102 R103 R104 R171 R206 TP4 TP5 TP6 TP7 TP8 TP9 U15
component class MCU114E2_GPIOs: EC1 EC2 R204 R205
component class MCU114E2_EtherCAT: C86 C87 C88 C89 C90 C91 C92 C93 C94 C95 C96 C97 C98 C99 C100 C101 C102 C103 C104 C105 C106 C107 C108 C109 C110 C111 C112 C113 C114 C115 C116 C117 D8 D9 J5 J6 R32 R58 R83 R84 R86 R87 R88 R89 R91 R92 R105 R106 R107 R108 R109 R110 R111 R112 R113 R114 R115 R116 R117 R118 R119 R120 R121 R122 R123 R124 R125 R126 R127 R128 R129 R130 R131 R132 R133 R134 R135 R136 R137 R138 R139 R140 R141 R142 R143 R144 R145 R146 R147 R148 R149 R150 R151 R152 R153 R154 R155 R156 R157 R158 R159 R160 R161 R162 R163 R166 R167 R168 R169 R170 R203 U16 U17 U18 U19 U25 U26
component class MCU114E2_Emulator_Interface: C30 C31 C34 C35 R1 R100 S1 U6 U7
component class MCU114E2_ADC: C62 C63 C118 C119 C120 C121 C122 C123 C124 C128 C129 C130 C131 C132 C133 C134 C135 C136 C137 C138 C139 C140 C141 C142 C143 C144 C145 C146 C147 C148 C149 C150 C151 R57 R172 R173 R174 R175 R176 R177 R178 R179 R180 R181 R182 R183 R184 R185 R186 R187 R188 R189 R190 R191 R192 R193 R194 R195 R196 R197 R198 R199 R200 R201 S5 S6 U1 U9 U20 U21 U22 U23 U24
differential pair MCU_D: +MCU_D_P -MCU_D_N
differential pair MCU_C10C11: +MCU_C10C11_P -MCU_C10C11_N
differential pair MCU_C2C3: +MCU_C2C3_P -MCU_C2C3_N
differential pair MCU_B4B5: +MCU_B4B5_P -MCU_B4B5_N
differential pair MCU_B2B3: +MCU_B2B3_P -MCU_B2B3_N
differential pair MCU_B0B1: +MCU_B0B1_P -MCU_B0B1_N
differential pair MCU_A14B14C14A15B15C15: +MCU_A14B14C14A15B15C15_P -MCU_A14B14C14A15B15C15_N
differential pair MCU_A10A11: +MCU_A10A11_P -MCU_A10A11_N
differential pair MCU_A8A9: +MCU_A8A9_P -MCU_A8A9_N
differential pair MCU_A4A5: +MCU_A4A5_P -MCU_A4A5_N
differential pair MCU_A2A3: +MCU_A2A3_P -MCU_A2A3_N
differential pair MCU_A0A1: +MCU_A0A1_P -MCU_A0A1_N
differential pair HSEC_ADC_C10C11: +HSEC_ADC_C10C11_P -HSEC_ADC_C10C11_N
differential pair HSEC_ADC_C2C3: +HSEC_ADC_C2C3_P -HSEC_ADC_C2C3_N
differential pair HSEC_ADC_B4B5: +HSEC_ADC_B4B5_P -HSEC_ADC_B4B5_N
differential pair HSEC_ADC_B2B3: +HSEC_ADC_B2B3_P -HSEC_ADC_B2B3_N
differential pair HSEC_ADC_B0B1: +HSEC_ADC_B0B1_P -HSEC_ADC_B0B1_N
differential pair HSEC_ADC_A14B14C14A15B15C15: +HSEC_ADC_A14B14C14A15B15C15_P -HSEC_ADC_A14B14C14A15B15C15_N
differential pair HSEC_ADC_A10A11: +HSEC_ADC_A10A11_P -HSEC_ADC_A10A11_N
differential pair HSEC_ADC_A8A9: +HSEC_ADC_A8A9_P -HSEC_ADC_A8A9_N
differential pair HSEC_ADC_A4A5: +HSEC_ADC_A4A5_P -HSEC_ADC_A4A5_N
differential pair HSEC_ADC_A2A3: +HSEC_ADC_A2A3_P -HSEC_ADC_A2A3_N
differential pair HSEC_ADC_A0A1: +HSEC_ADC_A0A1_P -HSEC_ADC_A0A1_N
differential pair XDS_D: +XDS_D_P -XDS_D_N
differential pair USB_D: +USB_D_P -USB_D_N
differential pair PHY1_TD: +PHY1_TD_P -PHY1_TD_N
differential pair PHY1_RD: +PHY1_RD_P -PHY1_RD_N
differential pair PHY0_TD: +PHY0_TD_P -PHY0_TD_N
differential pair PHY0_RD: +PHY0_RD_P -PHY0_RD_N

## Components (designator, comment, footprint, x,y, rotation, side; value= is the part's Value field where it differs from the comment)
B1 "LMK1C1104PW" PW0008A_N 5177.44,2602.69 r0 bottom
C1 "885012205031" 0402 2273.87,2786.69 r270 top value=0.01uF
C2 "885012205031" 0402 2560.09,2296.44 r90 top value=0.01uF
C3 "885012205031" 0402 2509.09,2296.44 r90 top value=0.01uF
C4 "885012205031" 0402 2458.09,2295.44 r90 top value=0.01uF
C5 "885012205037" 0402 2407.09,2295.44 r90 top value=0.1uF
C6 "885012205037" 0402 2356.09,2296.44 r90 top value=0.1uF
C7 "885012105012" 0402 2305.09,2296.44 r90 top value=1uF
C8 "885012105012" 0402 2538.87,2785.69 r180 top value=1uF
C9 "885012205031" 0402 2429.87,2784.69 r0 top value=0.01uF
C10 "885012105013" 0402 2567,2989 r90 bottom value=2.2uF
C11 "885012205037" 0402 2469,2989 r90 bottom value=0.1uF
C12 "885012105012" 0402 2518,2989 r90 bottom value=1uF
C13 "CL05C120JB5NNNC" 0402 2023,2811 r90 bottom value=12pF
C14 "CL05C120JB5NNNC" 0402 1973.87,2810.69 r90 bottom value=12pF
C15 "885012205037" 0402 1987.82,2429.57 r270 bottom value=0.1uF
C16 "885012205037" 0402 1985.87,2778.69 r90 top value=0.1uF
C17 "CC0603KRX5R7BB106" FP-CC0603KRX5R7BB106_0603-MFG 1924.81,2779.3 r270 top value=10µF
C18 "CC0603KRX5R7BB106" FP-CC0603KRX5R7BB106_0603-MFG 2162,2660 r180 top value=10µF
C19 "885012205031" 0402 2119,2392.38 r270 top value=0.01uF
C20 "CL05B332KB5NNNC" FP-CL388-IPC_C 1934.19,3172.07 r180 bottom
C21 "CC0603KRX5R7BB106" FP-CC0603KRX5R7BB106_0603-MFG 2552.66,3194.5 r90 bottom value=10µF
C22 "885012205037" 0402 2423.63,3207.55 r90 bottom value=0.1uF
C23 "885012205037" 0402 3096,3211 r180 top value=0.1uF
C24 "CC0603KRX5R7BB106" FP-CC0603KRX5R7BB106_0603-MFG 3096.39,3151.14 r0 top value=10µF
C25 "885012205037" 0402 3095.83,3091.27 r180 top value=0.1uF
C26 "CC0603KRX5R7BB106" FP-CC0603KRX5R7BB106_0603-MFG 2978,2816 r180 top value=10µF
C27 "885012205037" 0402 2972,2826 r180 bottom value=0.1uF
C28 "CC0603KRX5R7BB106" FP-CC0603KRX5R7BB106_0603-MFG 2971,2922 r0 bottom value=10µF
C29 "885012205037" 0402 3118.87,3029.69 r180 bottom value=0.1uF
C30 "885012205037" 0402 2538.83,2712.27 r180 top value=0.1uF
C31 "885012205037" 0402 2994,2690 r0 top value=0.1uF
C32 "885012106018" 0603 3142.09,1947.07 r180 bottom value=2.2uF
C33 "885012106018" 0603 3166.16,1668.98 r270 bottom value=2.2uF
C34 "C1812C100JHGACTU" 1812_180 1871.87,2127.08 r90 bottom value=10pF
C35 "885012205037" 0402 3319,2419 r270 bottom value=0.1uF
C36 "885012205037" 0402 4291.19,3264.69 r90 top value=0.1uF
C37 "885012205037" 0402 4238.83,2380.27 r90 top value=0.1uF
C38 "885012205037" 0402 4049,1423 r90 bottom value=0.1uF
C39 "885012205037" 0402 3744,2986 r180 top value=0.1uF
C40 "885012205037" 0402 3886,3135 r270 top value=0.1uF
C41 "885012205037" 0402 4068,2569 r90 top value=0.1uF
C42 "885012205037" 0402 3983,2570 r90 top value=0.1uF
C43 "885012205037" 0402 5432.44,2683.69 r0 bottom value=0.1uF
C44 "CL05B332KB5NNNC" FP-CL388-IPC_C 3552.78,3118.69 r0 bottom
C45 "885012106012" FP-885012106012_0603-MFG 3641.87,2540.69 r180 bottom value=4.7µF
C46 "293D104X9035A2TE3" 3216-18 3430.87,2681.69 r180 bottom value=0.1uF
C47 "TLJA686M010R1500" 3216-18 3430,2582 r180 bottom value=68uF
C48 "885012006032" FP-885012006032_0603-MFG 5507,1633 r270 bottom value=10pF
C49 "GRM188R61A226ME15D" 0603 5248,1636 r270 bottom value=22uF
C50 "885012006032" FP-885012006032_0603-MFG 5506,2033 r90 bottom value=10pF
C51 "885012205037" 0402 3778.81,3069.37 r90 top value=0.1uF
C52 "885012205037" 0402 5220,1879 r0 bottom value=0.1uF
C53 "CC0603KRX5R7BB106" FP-CC0603KRX5R7BB106_0603-MFG 5226,1941 r0 bottom value=10µF
C54 "CC0603KRX5R7BB106" FP-CC0603KRX5R7BB106_0603-MFG 5222.56,1769 r0 bottom value=10µF
C55 "885012205037" 0402 3491.09,2276.07 r90 bottom value=0.1uF
C56 "885012205037" 0402 3490.54,2172.03 r270 bottom value=0.1uF
C57 "885012205037" 0402 3780,2433 r90 bottom value=0.1uF
C58 "885012205037" 0402 3631.54,2095.03 r0 bottom value=0.1uF
C59 "885012205037" 0402 3830.04,2432.35 r90 bottom value=0.1uF
C60 "885012205037" 0402 3880.07,2432.55 r90 bottom value=0.1uF
C61 "885012205037" 0402 3489.09,2006.07 r270 bottom value=0.1uF
C62 "885012206046" 0603 2996,1731 r0 bottom value=0.1uF
C63 "885012106012" FP-885012106012_0603-MFG 3023.41,1970.12 r180 top value=4.7µF
C64 "885012106018" 0603 4024.71,2060.27 r180 bottom value=2.2uF
C65 "885012106018" 0603 4024,2211 r0 bottom value=2.2uF
C66 "885012106018" 0603 3379,1668.98 r270 bottom value=2.2uF
C67 "885012106018" 0603 3229,1668.98 r270 bottom value=2.2uF
C68 "885012205037" 0402 3123.09,1759.77 r180 bottom value=0.1uF
C69 "885012205037" 0402 3159.09,2095.03 r180 bottom value=0.1uF
C70 "885012205037" 0402 3527.54,2095.03 r180 bottom value=0.1uF
C71 "885012205037" 0402 3410.59,2095.03 r0 bottom value=0.1uF
C72 "885012205037" 0402 3059.23,2346.14 r180 bottom value=0.1uF
C73 "885012205037" 0402 3170.71,2418.45 r90 bottom value=0.1uF
C74 "885012205037" 0402 3059.5,2395.09 r180 bottom value=0.1uF
C75 "885012205037" 0402 3123.09,1810.07 r180 bottom value=0.1uF
C76 "885012205037" 0402 3059,2297 r180 bottom value=0.1uF
C77 "885012205037" 0402 3307.15,2095.03 r180 bottom value=0.1uF
C78 "885012205037" 0402 3719.09,1794.07 r0 bottom value=0.1uF
C79 "885012205037" 0402 3154,2004 r180 bottom value=0.1uF
C80 "885012205037" 0402 3269.67,2418.55 r90 bottom value=0.1uF
C81 "885012205037" 0402 3220.33,2418.55 r90 bottom value=0.1uF
C82 "885012205037" 0402 3719.09,1864.07 r0 bottom value=0.1uF
C83 "885012205037" 0402 3123,1859 r180 bottom value=0.1uF
C84 "CC0603KRX5R7BB106" FP-CC0603KRX5R7BB106_0603-MFG 4241,2346 r180 bottom value=10µF
C85 "CC0603KRX5R7BB106" FP-CC0603KRX5R7BB106_0603-MFG 4125.83,2281.61 r270 bottom value=10µF
C86 "885012205037" 0402 3614,2785.19 r270 top value=0.1uF
C87 "885012205086" FP-885012205086_0402-MFG 4935,2903 r180 bottom value=100nF
C88 "GRM155R61E105KE11D" 0402 4936,2851.84 r180 bottom value=1uF
C89 "C1005X5R1V225K050BC" 0402_065 4632.44,2697.86 r0 top value=2.2uF
C90 "885012205037" 0402 4631.83,2745.27 r0 top value=0.1uF
C91 "885012005053" FP-885012005053_0402-MFG 4831,2946 r0 bottom value=4.7pF
C92 "885012005053" FP-885012005053_0402-MFG 4831,2994 r0 bottom value=4.7pF
C93 "885012005053" FP-885012005053_0402-MFG 4793,2715.29 r270 bottom value=4.7pF
C94 "885012005053" FP-885012005053_0402-MFG 4838,2856 r0 bottom value=4.7pF
C95 "885012205086" FP-885012205086_0402-MFG 4876,2749 r180 bottom value=100nF
C96 "GRM155R61E105KE11D" 0402 4876,2802 r180 bottom value=1uF
C97 "GRM188R61A226ME15D" 0603 4595.08,2648.79 r270 bottom value=22uF
C98 "885012205037" 0402 4655.66,2658.58 r270 bottom value=0.1uF
C99 "GRM188R60J476ME15D" 0603 4359.83,3023.27 r90 top value=47uF
C100 "885012205037" 0402 4414.83,3024.27 r90 top value=0.1uF
C101 "885012205067" FP-885012205067_0402-MFG 5502.4,3188.82 r270 top value=10nF
C102 "885012205086" FP-885012205086_0402-MFG 4864.06,2056.26 r180 bottom value=100nF
C103 "885012205037" 0402 5132.44,2328.69 r90 top value=0.1uF
C104 "GRM155R61E105KE11D" 0402 4863,2007 r180 bottom value=1uF
C105 "C1005X5R1V225K050BC" 0402_065 4631.83,1857.27 r0 top value=2.2uF
C106 "885012205037" 0402 4632.44,1905.47 r0 top value=0.1uF
C107 "885012005053" FP-885012005053_0402-MFG 4766.92,2088.77 r90 bottom value=4.7pF
C108 "885012005053" FP-885012005053_0402-MFG 4685.39,2065.58 r90 bottom value=4.7pF
C109 "885012005053" FP-885012005053_0402-MFG 4759,1961 r90 bottom value=4.7pF
C110 "885012005053" FP-885012005053_0402-MFG 4651.3,1984.21 r180 bottom value=4.7pF
C111 "885012205086" FP-885012205086_0402-MFG 4864,1958 r180 bottom value=100nF
C112 "GRM155R61E105KE11D" 0402 4864.83,1908.5 r180 bottom value=1uF
C113 "GRM188R61A226ME15D" 0603 4518,1957 r90 bottom value=22uF
C114 "885012205037" 0402 4681.65,1897.19 r90 bottom value=0.1uF
C115 "GRM188R60J476ME15D" 0603 4225.7,2077.48 r90 bottom value=47uF
C116 "885012205037" 0402 4280.98,2065.11 r270 bottom value=0.1uF
C117 "885012205067" FP-885012205067_0402-MFG 5504.44,1515 r90 top value=10nF
C118 "885012106012" FP-885012106012_0603-MFG 3360.3,1703.43 r90 top value=4.7µF
C119 "885012106012" FP-885012106012_0603-MFG 3023.03,2039.58 r180 top value=4.7µF
C120 "885012106018" 0603 2995,1794 r0 bottom value=2.2uF
C121 "885012206052" 0603 3036.87,1537.69 r90 bottom value=1uF
C122 "885012206052" 0603 3293,1700 r270 top value=1uF
C123 "885012206052" 0603 3191,1667 r0 top value=1uF
C124 "885012206046" 0603 2996,1668 r0 bottom value=0.1uF
C125 "GRM188R61A226ME15D" 0603 5245.44,2044.69 r90 bottom value=22uF
C126 "885012205037" 0402 4536,2164 r90 top value=0.1uF
C128 "C0603C331J5GACTU" 0603 2009.15,1870.88 r90 top value=330pF
C129 "C0603C331J5GACTU" 0603 2133.34,1870.88 r90 top value=330pF
C130 "C0603C331J5GACTU" 0603 2257.52,1870.88 r90 top value=330pF
C131 "C0603C331J5GACTU" 0603 2505.88,1869.88 r90 bottom value=330pF
C132 "C0603C331J5GACTU" 0603 2630.05,1870.88 r90 bottom value=330pF
C133 "C0603C331J5GACTU" 0603 2382.06,1870.88 r90 top value=330pF
C134 "C0603C331J5GACTU" 0603 2009.15,1869.88 r90 bottom value=330pF
C135 "C0603C331J5GACTU" 0603 2133.34,1869.88 r90 bottom value=330pF
C136 "C0603C331J5GACTU" 0603 2257.52,1869.88 r90 bottom value=330pF
C137 "C0603C331J5GACTU" 0603 2505.88,1870.88 r90 top value=330pF
C138 "C0603C331J5GACTU" 0603 2319.61,1869.88 r90 bottom value=330pF
C139 "C0603C331J5GACTU" 0603 2630.06,1870.88 r90 top value=330pF
C140 "C0603C331J5GACTU" 0603 1947.06,1870.88 r90 top value=330pF
C141 "C0603C331J5GACTU" 0603 2071.24,1870.88 r90 top value=330pF
C142 "C0603C331J5GACTU" 0603 2195.43,1870.88 r90 top value=330pF
C143 "C0603C331J5GACTU" 0603 2443.79,1869.88 r90 bottom value=330pF
C144 "C0603C331J5GACTU" 0603 2567.97,1869.88 r90 bottom value=330pF
C145 "C0603C331J5GACTU" 0603 2320.06,1870.88 r90 top value=330pF
C146 "C0603C331J5GACTU" 0603 1947.06,1869.88 r90 bottom value=330pF
C147 "C0603C331J5GACTU" 0603 2071.24,1869.88 r90 bottom value=330pF
C148 "C0603C331J5GACTU" 0603 2195.43,1869.88 r90 bottom value=330pF
C149 "C0603C331J5GACTU" 0603 2443.79,1870.88 r90 top value=330pF
C150 "C0603C331J5GACTU" 0603 2381.7,1869.88 r90 bottom value=330pF
C151 "C0603C331J5GACTU" 0603 2567.97,1870.88 r90 top value=330pF
C152 "885012205037" 0402 5464.44,2606.69 r0 bottom value=0.1uF
C153 "885012205037" 0402 5470.81,2888.69 r0 bottom value=0.1uF
D1 "150080VS75000" WL-SMCW_Green_0805 2102.87,2789.69 r270 top value="Bright Green"
D1:A "1N5819HW-7-F" SOD-123 3115.83,3007.27 r180 top value=40V
D2 "150080SS75000" WL-SMCW_RED_0805 3328.6,2843.6 r180 top value=Red
D2:A "1N5819HW-7-F" SOD-123 3114.83,3288.27 r180 top value=40V
D3 "150080SS75000" WL-SMCW_RED_0805 4124.87,2452.69 r180 bottom value=Red
D4 "150080SS75000" WL-SMCW_RED_0805 4338.83,2452.27 r0 bottom value=Red
D5 "LTST-C170TBKT" LTST-C170TBKT_Blue 2650.87,3176.69 r90 bottom value=Blue
D6 "LTST-C170TBKT" LTST-C170TBKT_Blue 2732.83,3176.27 r90 bottom value=Blue
D7 "150080VS75000" WL-SMCW_Green_0805 5059.44,1831.69 r180 bottom value="Bright Green"
D8 "150080SS75000" WL-SMCW_RED_0805 5254.83,3190.27 r270 top value=Red
D9 "150080VS75000" WL-SMCW_Green_0805 5379.44,3189.69 r270 top value="Bright Green"
EC1 "controlCARD-120HSEC_Edge" controlCARD-120HSEC_Edge 2974.69,1040.78 r0 top locked
EC2 "controlCARD-180HSEC-60pinAddon_Edge" controlCARD-180HSEC-60pinAddon_Edge 5313.17,1040.78 r0 top locked
FID1 "Fiducial" Fiducial10-20#1 1795,1604 r0 top
FID2 "Fiducial" Fiducial10-20#1 1795,1604 r180 bottom
FID3 "Fiducial" Fiducial10-20#2 5703,1352 r0 top
FID4 "Fiducial" Fiducial10-20#2 5703,1352 r180 bottom
FID5 "Fiducial" Fiducial10-20#1 5071,3274 r0 top
FID6 "Fiducial" Fiducial10-20#1 5071,3274 r0 bottom
J1 "632723300011" Wurth_632_723_300_011 1717,3088 r270 top
J2 "2908-05WB-MG" 3M_2908-05WB-MG 4557.37,3145.39 r180 bottom
J3 "TMM-105-01-T-D" FP-TMM-105-01-T-D_HDR10-MFG 3826,1628 r0 top
J4 "632723300011" Wurth_632_723_300_011 3501,3364 r180 top
J5 "7498010210A" Wurth_7498010210A 5717.87,2765.69 r0 top
J6 "7498010210A" Wurth_7498010210A 5717.87,1904.03 r0 top
L1 "XFL4015-471MEC" XFL4015 5380.06,1665.69 r270 bottom value=470nH
L2 "XFL4015-471MEC" XFL4015 5380.06,2033.69 r90 bottom value=470nH
L3 "60 ohm" 0805_HV 4027.87,2135.69 r180 bottom
L4 "60 ohm" 0805_HV 3304,1683 r90 bottom
L5 "220 ohm" 0805_HV 4239.87,2253.69 r180 bottom
Logo1 "CE Mark" CE_Mark_5mm 5496.37,1384.27 r180 bottom
Logo2 "Texas Instruments" TI_Stacked_Overlay_Small 5353,3191 r180 bottom
Logo3 "FCC disclaimer" FCC_disclaimer 2341,2148 r0 top
Logo4 "WEEE logo" WEEE_Minimum 5227,1440 r180 bottom
Logo5 "ETHERCAT LABEL" EtherCAT_label 5999.95,1029.01 r90 top
R1 "AC0402FR-0710KL" 0402 2954.11,2492.58 r270 bottom value=10.0k
R2 "ERJ-2GE0R00X" 0402 5100.77,1709.69 r180 bottom value=0
R3 "CRCW04021K00JNED" 0402 2192.85,2471.64 r90 top value=1.0k
R4 "CRCW04021K00JNED" 0402 2241.87,2471.69 r90 top value=1.0k
R5 "CRCW04021K00JNED" 0402 2289.87,2471.69 r90 top value=1.0k
R6 "CRCW04021K00JNED" 0402 2337.87,2471.69 r90 top value=1.0k
R7 "CRCW0402100RJNED" 0402 2324,2786.69 r90 top value=100
R8 "ERJ-2RKF4700X" 0402 2676.09,3009.07 r270 bottom value=470
R9 "ERJ-2RKF4700X" 0402 2726,3009 r270 bottom value=470
R10 "AC0402FR-0710KL" 0402 2036.87,2533.69 r90 bottom value=10.0k
R11 "AC0402FR-0710KL" 0402 2037.05,2429.61 r90 bottom value=10.0k
R12 "CRCW04024K87FKED" 0402 2254.09,2296.44 r270 top value=4.87k
R13 "51" FP-RT0402FRE0751RL_0402-MFG 1982,2534 r90 bottom
R14 "CRCW0402680RJNED" 0402 2034.87,2778.69 r270 top value=680
R15 "RMCF0402FT1M00" 0402 1930.09,3110.07 r0 bottom value=1.00Meg
R16 "RC0603JR-075K1L" 0603 2351,3000.98 r90 bottom value=5.1k
R17 "RC0603JR-075K1L" 0603 2413,3000.98 r270 bottom value=5.1k
R18 "ERJ-3GEY0R00V" 0603 2485.09,3195.44 r270 bottom value=0
R19 "CRCW06032K20JNEA" 0603 2983,2910 r180 top value=2.2k
R20 "ERJ-3GEY0R00V" 0603 2983,2746.97 r180 top value=0
R21 "RC0603FR-071KL" 0603 3196,2714.07 r180 top value=1.00k
R22 "CRCW060310K0JNEA" 0603 2983.54,2770.95 r0 bottom value=10k
R23 "CRCW060310K0JNEA" 0603 3116.87,2973.69 r0 bottom value=10k
R24 "RC0603JR-074K7L" 0603 3238.03,3150.9 r180 bottom value=4.7k
R25 "RC0603FR-07430RL" 0603 3197,2776 r180 top value=430
R26 "RC0603JR-071K2L" 0603 3238.03,3088.9 r0 bottom value=1.2k
R27 "ERJ-3GEY0R00V" 0603 3230,2872 r90 top value=0
R28 "ERJ-3GEY0R00V" 0603 3239,3238 r180 bottom value=0
R29 "ERJ-3GEY0R00V" 0603 3239,3302 r180 bottom value=0
R30 "CRCW040288K7FKED" 0402 5595.01,1698.59 r180 bottom value=88.7k
R31 "AC0402FR-0710KL" 0402 3718,2897 r90 bottom value=10.0k
R32 "CRG0402F4K7" 0402 4631.82,2650.45 r0 top value=4.70k
R33 "ERJ-3GEY0R00V" 0603 3818.8,2662.39 r270 top value=0
R34 "CRCW0402680RJNED" 0402 4032.87,2459.69 r270 bottom value=680
R35 "CRCW0402680RJNED" 0402 4432.87,2461.69 r270 bottom value=680
R36 "AC0402FR-0710KL" 0402 4348.51,3264.69 r90 top value=10.0k
R37 "AC0402FR-0710KL" 0402 4405.83,3266.27 r90 top value=10.0k
R38 "AC0402FR-0710KL" 0402 4195.88,1747.27 r0 top value=10.0k
R39 "CRCW04021M50JNED" 0402 4053.37,2434.27 r180 top value=1.5Meg
R40 "CRCW04021M50JNED" 0402 4214.28,2258 r0 top value=1.5Meg
R41 "RG1005P-104-B-T5" 0402 4585,2164.27 r90 top value=100k
R42 "CRCW04023K30JNED" 0402 4098,1423 r270 bottom value=3.3k
R43 "AC0402FR-0710KL" 0402 4233.87,3264.69 r270 top value=10.0k
R44 "ERJ-3GEY0R00V" 0603 4016,2837 r90 top value=0
R45 "ERJ-3GEY0R00V" 0603 3727.66,1462.27 r270 top value=0
R46 "ERJ-2GE0R00X" 0402 4031,2063 r90 top value=0
R47 "ERJ-3GEY0R00V" 0603 3791.96,1462.27 r270 top value=0
R48 "CRCW04020000Z0EDHP" 0402 3981.65,2062.43 r90 top value=0
R49 "ERJ-3GEY0R00V" 0603 4197,3154 r180 top value=0
R50 "ERJ-3GEY0R00V" 0603 3856.25,1462.27 r270 top value=0
R51 "AC0402FR-0710KL" 0402 3983.87,2674.69 r90 top value=10.0k
R52 "ERJ-3GEY0R00V" 0603 3881,2663 r90 top value=0
R53 "CRCW0603100KJNEA" 0603 5734.44,1871.6 r0 bottom value=100k
R54 "AC0402FR-0710KL" 0402 3936.87,2674.69 r90 top value=10.0k
R55 "ERJ-3GEY0R00V" 0603 4228.43,3057.19 r90 top value=0
R56 "ERJ-3GEY0R00V" 0603 3984.83,1462.27 r270 top value=0
R57 "RC0603FR-071KL" 0603 3191.48,1733.4 r180 top value=1.00k
R58 "ERJ-2GE0R00X" 0402 4209,2698.74 r180 top value=0
R59 "ERJ-3GEY0R00V" 0603 4611.88,2414.22 r270 bottom value=0
R60 "ERJ-3GEY0R00V" 0603 4673.45,2459.67 r90 bottom value=0
R61 "CRCW04023K30JNED" 0402 4129,3079 r90 bottom value=3.3k
R62 "CRCW040256K0JNED" 0402 5516,2298 r90 bottom value=56k
R63 "CRCW040256K0JNED" 0402 5152.94,2298 r90 bottom value=56k
R64 "ERJ-3GEY0R00V" 0603 4734.44,2414.22 r270 bottom value=0
R65 "CPF0402B10RE1" CPF0402 5084.44,2712.84 r90 bottom value=10.0
R66 "ERJ-3GEY0R00V" 0603 4798,2459.5 r90 bottom value=0
R67 "CPF0402B10RE1" CPF0402 5363.44,2526.69 r270 bottom value=10.0
R68 "CPF0402B10RE1" CPF0402 5232.44,2712.84 r90 bottom value=10.0
R69 "CRCW04020000Z0EDHP" 0402 5574.83,2533.65 r270 bottom value=0
R70 "ERJ-3GEY0R00V" 0603 4489.25,2414.22 r90 bottom value=0
R71 "CRCW04020000Z0EDHP" 0402 3343,2807 r90 bottom value=0
R72 "AC0402FR-0710KL" 0402 3393,2807 r90 bottom value=10.0k
R73 "ERJ-2GE0R00X" 0402 5134.44,2722.41 r270 bottom value=0
R74 "CRCW04020000Z0EDHP" 0402 5183,2723 r90 bottom value=0
R75 "ERJ-3GEY0R00V" 0603 4548.44,2459.67 r90 bottom value=0
R76 "CRCW04020000Z0EDHP" 0402 5587.83,2813.27 r270 bottom value=0
R77 "RMCF0402FT1M00" 0402 3435.78,3117.69 r0 bottom value=1.00Meg
R78 "ERJ-3GEY0R00V" 0603 4165,3057 r90 top value=0
R79 "RC0603JR-075K1L" 0603 3588.82,2937.82 r180 bottom value=5.1k
R80 "ERJ-2GE0R00X" 0402 3810,2849 r0 bottom value=0
R81 "ERJ-2GE0R00X" 0402 3811,2799.19 r0 bottom value=0
R82 "ERJ-2GE0R00X" 0402 4022.83,2200 r180 top value=0
R83 "ERJ-2GE0R00X" 0402 4381.22,2592.69 r270 top value=0
R84 "ERJ-2GE0R00X" 0402 4332.83,2592.69 r270 top value=0
R85 "ERJ-6GEYJ103V" 0805_HV 3818.83,2667.89 r0 bottom value=10k
R86 "ERJ-2GE0R00X" 0402 4284.44,2592.69 r270 top value=0
R87 "ERJ-2GE0R00X" 0402 4209,2650.69 r180 top value=0
R88 "CRCW04022K49FKED" 0402 4084,2737 r180 bottom value=2.49k
R89 "CRCW04022K49FKED" 0402 4667,3231 r0 top value=2.49k
R90 "CRCW0603100KJNEA" 0603 3611.89,2740.22 r180 bottom value=100k
R91 "ERJ-2GE0R00X" 0402 4195.88,1845.03 r180 top value=0
R92 "ERJ-2GE0R00X" 0402 4376.58,1746.69 r270 top value=0
R93 "ERJ-2GE0R00X" 0402 3719,3146.12 r90 bottom value=0
R94 "CRCW0402680RJNED" 0402 5100.77,1760.69 r0 bottom value=680
R95 "CRCW040219K6FKED" 0402 5596,1649 r0 bottom value=19.6k
R96 "ERJ-3GEY0R00V" 0603 3663.44,1462.27 r90 top value=0
R97 "ERJ-2GE0R00X" 0402 5594.81,1798.69 r0 bottom value=0
R98 "ERJ-3GEY0R00V" 0603 3920.61,1462.27 r90 top value=0
R99 "ERJ-2GE0R00X" 0402 5220.46,1829.26 r180 bottom value=0
R100 "AC0402FR-0710KL" 0402 3075,2464 r270 top value=10.0k
R101 "ERJ-2GE0R00X" 0402 5100.77,2047.69 r180 bottom value=0
R102 "CRCW040268K0JNED" 0402 5595.49,2047.89 r0 bottom value=68k
R103 "AC0402FR-0710KL" 0402 5595,1749 r0 bottom value=10.0k
R104 "CRCW0603100KJNEA" 0603 5735,1808 r180 bottom value=100k
R105 "CRG0402F4K7" 0402 3813,2549.62 r0 bottom value=4.70k
R106 "CRG0402F4K7" 0402 3812,2598.62 r0 bottom value=4.70k
R107 "CRCW04022K20FKED" 0402 4684.57,3025.27 r90 top value=2.20k
R108 "CRG0402F4K7" 0402 4209,2794.84 r0 top value=4.70k
R109 "CRCW04026K49FKED" 0402 4732,3025.27 r270 top value=6.49k
R110 "ERJ-2GE0R00X" 0402 4327.29,1746.69 r270 top value=0
R111 "CRCW04022K49FKED" 0402 4562,3231 r180 top value=2.49k
R112 "CRCW04022K49FKED" 0402 4112.21,2828.53 r270 bottom value=2.49k
R113 "CRCW04022K49FKED" 0402 4831.44,3107.81 r180 bottom value=2.49k
R114 "CRCW040233R2FKED" 0402 4209,2890.95 r0 top value=33.2
R115 "CRCW040233R2FKED" 0402 4209,2939 r0 top value=33.2
R116 "CRCW040233R2FKED" 0402 4542.26,3025.27 r270 top value=33.2
R117 "CRCW040233R2FKED" 0402 4589.7,3025.27 r270 top value=33.2
R118 "CRCW040233R2FKED" 0402 4637.13,3025.27 r270 top value=33.2
R119 "CRCW040233R2FKED" 0402 4209,2842.9 r0 top value=33.2
R120 "CRCW040233R2FKED" 0402 4209,2746.79 r0 top value=33.2
R121 "CRCW040233R2FKED" 0402 4429.61,2592.69 r90 top value=33.2
R122 "CRCW040233R2FKED" 0402 4478,2592.69 r90 top value=33.2
R123 "CRCW04022K20FKED" 0402 4555,2504 r180 top value=2.20k
R124 "CRCW04022K20FKED" 0402 4554,2552 r180 top value=2.20k
R125 "CRCW04022K20FKED" 0402 4554,2600 r180 top value=2.20k
R126 "CRCW040233R2FKED" 0402 4494.83,3025.27 r270 top value=33.2
R127 "CRCW04022K49FKED" 0402 4197,2579.62 r270 bottom value=2.49k
R128 "CRCW04022K49FKED" 0402 4831.3,3059.59 r180 bottom value=2.49k
R129 "CRCW04022K49FKED" 0402 5066,2970 r90 bottom value=2.49k
R130 "CRCW04022K49FKED" 0402 4195.36,1988.33 r0 bottom value=2.49k
R131 "RMCF0402ZT0R00" "FP-RMCF0402ZT0R00_0402 (1005 metric)-0" 4694.83,2657.27 r90 bottom
R132 "CRCW0603470RJNEA" 0603 4728.44,2611.69 r270 top value=470
R133 "CRCW04022K49FKED" 0402 4465.68,2187.89 r0 bottom value=2.49k
R134 "RMCF0402ZT0R00" "FP-RMCF0402ZT0R00_0402 (1005 metric)-0" 4455.83,3022.27 r90 top
R135 "CRCW0603470RJNEA" 0603 4821.39,3121.83 r270 top value=470
R136 "RMCF0402FT1M00" 0402 5552.44,3188.69 r270 top value=1.00Meg
R137 "CRCW04021K27FKED" 0402 4947.44,2357.69 r180 top value=1.27k
R138 "CRCW0402680RJNED" 0402 4946.87,2307.69 r0 top value=680
R139 "CRCW04021M50JNED" 0402 5437.44,2300.69 r0 top value=1.5Meg
R140 "CRCW04021M50JNED" 0402 5435.44,2356.69 r0 top value=1.5Meg
R141 "CRG0402F4K7" 0402 4632.83,1808.27 r0 top value=4.70k
R142 "CRG0402F4K7" 0402 4196,1943 r0 top value=4.70k
R143 "CRCW04026K49FKED" 0402 4633.83,2164.27 r270 top value=6.49k
R144 "ERJ-2GE0R00X" 0402 4278,1746.69 r270 top value=0
R145 "CRCW04022K49FKED" 0402 4448.03,2296.69 r90 bottom value=2.49k
R146 "CRCW04022K49FKED" 0402 4096.24,1874.98 r270 bottom value=2.49k
R147 "CRCW04022K49FKED" 0402 4399,2297 r270 bottom value=2.49k
R148 "CRCW040233R2FKED" 0402 4195.88,2040.56 r0 top value=33.2
R149 "CRCW040233R2FKED" 0402 4195.88,2089.45 r0 top value=33.2
R150 "CRCW040233R2FKED" 0402 4389.66,2164.27 r270 top value=33.2
R151 "CRCW04022K20FKED" 0402 4551.44,1739.69 r0 top value=2.20k
R152 "CRCW040233R2FKED" 0402 4438.5,2164.27 r270 top value=33.2
R153 "CRCW040233R2FKED" 0402 4487.33,2164.27 r270 top value=33.2
R154 "CRCW040233R2FKED" 0402 4195.88,1991.68 r0 top value=33.2
R155 "CRCW040233R2FKED" 0402 4195.88,1893.92 r0 top value=33.2
R156 "CRCW040233R2FKED" 0402 4425.87,1746.69 r90 top value=33.2
R157 "CRCW040233R2FKED" 0402 4475.16,1746.69 r90 top value=33.2
R158 "CRCW040233R2FKED" 0402 4340.83,2164.27 r270 top value=33.2
R159 "CRCW04022K20FKED" 0402 4553.44,1642.69 r180 top value=2.20k
R160 "CRCW04022K20FKED" 0402 4552.44,1691.69 r180 top value=2.20k
R161 "CRCW04022K49FKED" 0402 4129.83,2066.69 r90 bottom value=2.49k
R162 "CRCW04022K49FKED" 0402 4350,2297 r270 bottom value=2.49k
R163 "CRCW04022K49FKED" 0402 4632.83,1786.61 r0 bottom value=2.49k
R166 "RMCF0402ZT0R00" "FP-RMCF0402ZT0R00_0402 (1005 metric)-0" 4722.83,1877.27 r90 bottom
R167 "CRCW0603470RJNEA" 0603 4728.44,1765.69 r270 top value=470
R168 "RMCF0402ZT0R00" "FP-RMCF0402ZT0R00_0402 (1005 metric)-0" 4179.99,2057.37 r90 bottom
R169 "CRCW0603470RJNEA" 0603 4802.83,2217.27 r180 top value=470
R170 "RMCF0402FT1M00" 0402 5552.44,1515 r90 top value=1.00Meg
R171 "CRCW040215K0FKED" 0402 5594.81,1903.69 r180 bottom value=15.0k
R172 "ERJ-3GEY0R00V" 0603 1948.04,1664.45 r270 top value=0
R173 "ERJ-3GEY0R00V" 0603 2010.13,1664.45 r270 top value=0
R174 "ERJ-3GEY0R00V" 0603 2072.04,1664.45 r270 top value=0
R175 "ERJ-3GEY0R00V" 0603 2134.31,1664.45 r270 top value=0
R176 "ERJ-3GEY0R00V" 0603 2196.4,1664.45 r270 top value=0
R177 "ERJ-3GEY0R00V" 0603 2258.49,1664.45 r270 top value=0
R178 "ERJ-3GEY0R00V" 0603 2443.78,1663.83 r270 bottom value=0
R179 "ERJ-3GEY0R00V" 0603 2505.87,1663.83 r270 bottom value=0
R180 "ERJ-3GEY0R00V" 0603 2567.96,1663.83 r270 bottom value=0
R181 "ERJ-3GEY0R00V" 0603 2631.04,1664.45 r270 bottom value=0
R182 "ERJ-3GEY0R00V" 0603 2320.58,1664.45 r270 top value=0
R183 "ERJ-3GEY0R00V" 0603 2382.67,1664.45 r270 top value=0
R184 "ERJ-3GEY0R00V" 0603 1948.04,1664.45 r270 bottom value=0
R185 "ERJ-3GEY0R00V" 0603 2010.13,1664.45 r270 bottom value=0
R186 "ERJ-3GEY0R00V" 0603 2071.23,1663.83 r270 bottom value=0
R187 "ERJ-3GEY0R00V" 0603 2133.33,1663.83 r270 bottom value=0
R188 "ERJ-3GEY0R00V" 0603 2195.42,1663.83 r270 bottom value=0
R189 "ERJ-3GEY0R00V" 0603 2257.51,1663.83 r270 bottom value=0
R190 "ERJ-3GEY0R00V" 0603 2444.76,1664.45 r270 top value=0
R191 "ERJ-3GEY0R00V" 0603 2506.85,1664.45 r270 top value=0
R192 "ERJ-3GEY0R00V" 0603 2381.69,1663.83 r270 bottom value=0
R193 "ERJ-3GEY0R00V" 0603 2319.6,1663.83 r270 bottom value=0
R194 "ERJ-3GEY0R00V" 0603 2568.95,1664.45 r270 top value=0
R195 "ERJ-3GEY0R00V" 0603 2631.04,1664.45 r270 top value=0
R196 "ERJ-3GEY0R00V" 0603 3337.83,1504.27 r90 bottom value=0
R197 "ERJ-3GEY0R00V" 0603 3484.83,1504.27 r90 bottom value=0
R198 "ERJ-3GEY0R00V" 0603 3411.33,1504.27 r90 bottom value=0
R199 "ERJ2BWFR100X" 0402 3024,1910 r0 top value=0.1
R200 "ERJ2BWFR100X" 0402 3436,1657 r90 bottom value=0.1
R201 "ERJ2BWFR100X" 0402 3025.16,2098.75 r0 top value=0.1
R202 "CRCW04022K20FKED" 0402 3774.87,1724.69 r0 bottom value=2.20k
R203 "ERJ-2GE0R00X" 0402 4195.88,1796.15 r180 top value=0
R204 "CRG0402F4K7" 0402 1882,1660.25 r90 top value=4.70k
R205 "CRG0402F4K7" 0402 1881.64,1660.93 r270 bottom value=4.70k
R206 "CRCW040268K0JNED" 0402 5594.81,1998.4 r180 bottom value=68k
R212 "ERJ-3GEY0R00V" 0603 4081.04,2837.28 r90 top value=0
S1 "218-2LPST" SW_218-2LP 3252.35,2595.26 r0 top
S2 "CAS-D20TA" SW_CAS-D20TA 3869,2838 r270 top
S3 "CAS-D20TA" SW_CAS-D20TA 5334.44,2288.69 r180 bottom
S4 "1188E-1K2-V-TR" SW_1188E 3963,3245 r270 top
S5 "CAS-D20TA" SW_CAS-D20TA 3503.32,1444.27 r90 top
S6 "CAS-D20TA" SW_CAS-D20TA 3255.47,1444.27 r90 top
T1 "750315371" Wurth_750315371 2754.87,3112.69 r180 top value=105uH
TP1 "TESTPOINT" TP_50MIL-25MILHOLE 1845.87,2638.69 r0 top
TP2 "TESTPOINT" TP_50MIL-25MILHOLE 1845.87,2382.69 r0 top
TP3 "TESTPOINT" TP_50MIL-25MILHOLE 2018.87,2275.69 r0 top
TP4 "TESTPOINT" TP_50MIL-25MILHOLE 1801,1729 r90 top
TP5 "TESTPOINT" TP_50MIL-25MILHOLE 1801,1939 r90 top
TP6 "TESTPOINT" TP_50MIL-25MILHOLE 4003,1810 r90 top
TP7 "TESTPOINT" TP_50MIL-25MILHOLE 4003.83,2313.27 r90 top
TP8 "TESTPOINT" TP_50MIL-25MILHOLE 1801,1834 r90 top
TP9 "TESTPOINT" TP_50MIL-25MILHOLE 3741.83,3278.27 r0 top
TP10 "TESTPOINT" TP_50MIL-25MILHOLE 3925.83,2239.27 r90 top
TP11 "TESTPOINT" TP_50MIL-25MILHOLE 4236,1656 r0 top
U1 "TMS320F28P650DK9ZEJ" ZEJ0256A-MFG 3489.82,2094.29 r0 top
U2 "MSP432E401YTPDT" PDT0128A 2410.85,2585.26 r180 bottom
U3 "SN6505BDBVR" DBV0006A_L 2370.09,3196.07 r180 top
U4 "TPD4E05U06DQAR" DQA0010A#1 2306.85,3038.26 r90 top
U5 "TPS2113ADRBR" DRB0008B 3122,2868.8 r180 bottom
U6 "ISO7762DBQR" DBQ0016A_N 2841.8,2560.06 r0 top
U7 "SN74CB3Q3244PWR" PW0020A-MFG 3167,2615 r0 bottom
U8 "TLV70333DBVR" DBV0005A-MFG 1976.87,2520.69 r0 top
U9 "TPD6E05U06RVZR" RVZ0014A 2179.87,1444.69 r90 top
U10 "SN74LVC2G07DBVR" DBV0006A_N 4133.87,2339.69 r0 top
U11 "TPS3703A4330DSERQ1" DSE0006A 3846.79,2993.27 r0 top
U12 "TPS3850G12QDRCRQ1" DRC0010R 3992.44,3054.69 r0 top
U13 "TPD4E05U06DQAR" DQA0010A#2 3482.69,2821.56 r90 bottom
U14 "TPS2051BDBVR" DBV0005A_N 3624,2644 r180 bottom
U15 "TPS62442WRQRR" RQR0014A-MFG 5404.44,1850.69 r180 bottom
U16 "CAT24C16WI-GT3" SOIC-8 3581,2628 r0 top
U17 "TPD4E05U06DQAR" DQA0010A#1 4651.3,2830.21 r0 top
U18 "SN74LVC2G06DBVR" DBV0006A_N 5252.44,2332.69 r180 top
U19 "TPD4E05U06DQAR" DQA0010A#1 4647.98,1992.82 r0 top
U20 "TPD6E05U06RVZR" RVZ0014A 2500.87,1444.69 r90 top
U21 "TPD6E05U06RVZR" RVZ0014A 2501.94,1443.62 r270 bottom
U22 "TPD6E05U06RVZR" RVZ0014A 2180.94,1443.62 r270 bottom
U23 "REF5030AIDR" D0008A_N 2986,1539 r0 top
U24 "OPA4350EA/250" DBQ0016A_N 2983.83,1772.27 r0 top
U25 "DP83826IRHBR" RHB0032M-MFG 4436.44,2800.69 r180 top
U26 "DP83826IRHBR" RHB0032M-MFG 4436.44,1954.69 r180 top
Y1 "830064296" FP-830064296_SMT4_3MM4_2MM7-MFG 1875,2797 r90 bottom
Y2 "PLMK6CE02500CDLFT" DLF0004A-MFG 5466.6,2528.69 r180 bottom
Y3 "PLMK6CE02000CDLFT" DLF0004A-MFG 5466.6,2810.69 r180 bottom
ZZ1 "This Assembly Note is for PCB labels only" AssemblyNoteLabel -1031,4415 r0 top
ZZ2 "These assemblies are ESD sensitive, ESD precautions shall be observed." AssemblyNote -1032,4313 r0 top
ZZ3 "These assemblies must be clean and free from flux and all contaminants. Use of no clean flux is not acceptable." AssemblyNote -1036,4207 r0 top
ZZ4 "These assemblies must comply with workmanship standards IPC-A-610 Class 2, unless otherwise specified." AssemblyNote -1041,4109 r0 top

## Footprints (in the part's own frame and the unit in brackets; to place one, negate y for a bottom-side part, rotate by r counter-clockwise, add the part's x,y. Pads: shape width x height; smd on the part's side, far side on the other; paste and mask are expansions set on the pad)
3M_2908-05WB-MG [mm] "Connector, Micro SD, R/A, SMD"
  rect 0.8x1.5 smd: 1(0,0) 2(1.1,-0.4) 3(2.2,0) 4(3.3,0.2) 5(4.4,0) 6(5.5,0.2) 7(6.6,0) 8(7.7,0)
  rect 1.4x1.9 smd: S1(-4.66,3.85) S2(8.49,2.85)
  rect 1.8x1.4 smd: S3(6.89,-10.3) S4(1.19,-10.3)
  silkscreen extent -5.06,-10.7 8.94,4.45, body extent -5.06,-10.75 8.94,4.5, height 1.91
0402 [mm] "0402 from SM-752 data"
  rect 0.8x0.6 smd: 1(-0.6,0) 2(0.6,0)
  silkscreen extent -1.22,-0.52 1.22,0.52, body extent -0.55,-0.3 0.55,0.3, height 0.6
0402_065 [mm] "0402"
  rect 0.8x0.6 smd: 1(-0.6,0) 2(0.6,0)
  silkscreen extent -1.22,-0.52 1.22,0.52, body extent -0.55,-0.3 0.55,0.3, height 0.65
0603 [mm] "0603 from SM-752 data"
  rect 1x0.95 smd: 1(-0.8,0) 2(0.8,0)
  silkscreen extent -1.52,-0.69 1.52,0.69, body extent -0.87,-0.47 0.87,0.47, height 1
0805_HV [mil] "0805 with 30mil clearance between pads"
  rect 50x63 smd: 1(-40,0) 2(40,0)
  silkscreen extent -74,-40 74,40, body extent -43,-29 43,29, height 57
1812_180 [mil] "SMT, 2-Leads, Body 4.5x3.2mm"
  rect 58x171.65 smd: 1(-109.61,0) 2(109.61,0)
  silkscreen extent -148,-98 148,98, body extent -95,-69 95,69, height 71
3216-18 [mm] "Based on AVX recommendation in http://www.avx.com/download/software/literature/AVX-Footprint-Library.pdf"
  rrect7% 1.4x1.8 smd: 1(-1.3,0) 2(1.3,0)
  silkscreen extent -1.9,-1.12 0.8,1.12, body extent -1.7,-0.9 1.7,0.9, height 1.82
AssemblyNote [mil] "Assembly Note"
AssemblyNoteLabel [mil] "Assembly Note for PCB Labels"
CE_Mark_5mm [mil] "Minimum text height for CE Mark"
  silkscreen extent -138,-98 138,98
controlCARD-120HSEC_Edge [mm] "Edge Connector, 0.8mm, 60x2, pad numbers do not match Samtec datasheet"
  rect 0.55x2.8 smd paste-2.5 mask+0: 1(-23.6,2.4) 3(-22.8,2.4) 5(-22,2.4) 7(-21.2,2.4) 9(-20.4,2.4) 11(-19.6,2.4) 13(-18.8,2.4) 15(-18,2.4) 17(-17.2,2.4) 19(-16.4,2.4) 21(-15.6,2.4) 23(-14.8,2.4) 25(-14,2.4) 27(-13.2,2.4) 29(-12.4,2.4) 31(-11.6,2.4) 33(-10.8,2.4) 35(-10,2.4) 37(-9.2,2.4) 39(-8.4,2.4) 41(-7.6,2.4) 43(-6.8,2.4) 45(-6,2.4) 47(-5.2,2.4) 49(-4.4,2.4) 51(-3.6,2.4) 53(-2.8,2.4) 55(-2,2.4) 57(2,2.4) 59(2.8,2.4) 61(3.6,2.4) 63(4.4,2.4) 65(5.2,2.4) 67(6,2.4) 69(6.8,2.4) 71(7.6,2.4) 73(8.4,2.4) 75(9.2,2.4) 77(10,2.4) 79(10.8,2.4) 81(11.6,2.4) 83(12.4,2.4) 85(13.2,2.4) 87(14,2.4) 89(14.8,2.4) 91(15.6,2.4) 93(16.4,2.4) 95(17.2,2.4) 97(18,2.4) 99(18.8,2.4) 101(19.6,2.4) 103(20.4,2.4) 105(21.2,2.4) 107(22,2.4) 109(22.8,2.4) 111(23.6,2.4) 113(24.4,2.4) 115(25.2,2.4) 117(26,2.4) 119(26.8,2.4)
  rect 0.55x2.8 smd far side paste-2.5 mask+0: 2(-23.6,2.4) 4(-22.8,2.4) 6(-22,2.4) 8(-21.2,2.4) 10(-20.4,2.4) 12(-19.6,2.4) 14(-18.8,2.4) 16(-18,2.4) 18(-17.2,2.4) 20(-16.4,2.4) 22(-15.6,2.4) 24(-14.8,2.4) 26(-14,2.4) 28(-13.2,2.4) 30(-12.4,2.4) 32(-11.6,2.4) 34(-10.8,2.4) 36(-10,2.4) 38(-9.2,2.4) 40(-8.4,2.4) 42(-7.6,2.4) 44(-6.8,2.4) 46(-6,2.4) 48(-5.2,2.4) 50(-4.4,2.4) 52(-3.6,2.4) 54(-2.8,2.4) 56(-2,2.4) 58(2,2.4) 60(2.8,2.4) 62(3.6,2.4) 64(4.4,2.4) 66(5.2,2.4) 68(6,2.4) 70(6.8,2.4) 72(7.6,2.4) 74(8.4,2.4) 76(9.2,2.4) 78(10,2.4) 80(10.8,2.4) 82(11.6,2.4) 84(12.4,2.4) 86(13.2,2.4) 88(14,2.4) 90(14.8,2.4) 92(15.6,2.4) 94(16.4,2.4) 96(17.2,2.4) 98(18,2.4) 100(18.8,2.4) 102(19.6,2.4) 104(20.4,2.4) 106(21.2,2.4) 108(22,2.4) 110(22.8,2.4) 112(23.6,2.4) 114(24.4,2.4) 116(25.2,2.4) 118(26,2.4) 120(26.8,2.4)
controlCARD-180HSEC-60pinAddon_Edge [mm] "Edge Connector, 0.8mm, 30x2, pad numbers do not match Samtec datasheet"
  rect 0.55x2.8 smd paste-2.5 mask+0: 121(-11.6,2.4) 123(-10.8,2.4) 125(-10,2.4) 127(-9.2,2.4) 129(-8.4,2.4) 131(-7.6,2.4) 133(-6.8,2.4) 135(-6,2.4) 137(-5.2,2.4) 139(-4.4,2.4) 141(-3.6,2.4) 143(-2.8,2.4) 145(-2,2.4) 147(-1.2,2.4) 149(-0.4,2.4) 151(0.4,2.4) 153(1.2,2.4) 155(2,2.4) 157(2.8,2.4) 159(3.6,2.4) 161(4.4,2.4) 163(5.2,2.4) 165(6,2.4) 167(6.8,2.4) 169(7.6,2.4) 171(8.4,2.4) 173(9.2,2.4) 175(10,2.4) 177(10.8,2.4) 179(11.6,2.4)
  rect 0.55x2.8 smd far side paste-2.5 mask+0: 122(-11.6,2.4) 124(-10.8,2.4) 126(-10,2.4) 128(-9.2,2.4) 130(-8.4,2.4) 132(-7.6,2.4) 134(-6.8,2.4) 136(-6,2.4) 138(-5.2,2.4) 140(-4.4,2.4) 142(-3.6,2.4) 144(-2.8,2.4) 146(-2,2.4) 148(-1.2,2.4) 150(-0.4,2.4) 152(0.4,2.4) 154(1.2,2.4) 156(2,2.4) 158(2.8,2.4) 160(3.6,2.4) 162(4.4,2.4) 164(5.2,2.4) 166(6,2.4) 168(6.8,2.4) 170(7.6,2.4) 172(8.4,2.4) 174(9.2,2.4) 176(10,2.4) 178(10.8,2.4) 180(11.6,2.4)
CPF0402 [mm] "TE Connectivity"
  rect 0.5x0.6 smd: 1(-0.5,0) 2(0.5,0)
  silkscreen extent -0.97,-0.53 0.97,0.53, body extent -0.55,-0.27 0.55,0.27, height 0.35
D0008A_N [mm] "SOIC, 8-Leads, Body 4.9x3.9mm, Pitch 1.27mm, IPC Medium Density"
  oval 1.45x0.6 smd: 1(-2.725,1.905) 2(-2.725,0.635) 3(-2.725,-0.635) 4(-2.725,-1.905) 5(2.725,-1.905) 6(2.725,-0.635) 7(2.725,0.635) 8(2.725,1.905)
  silkscreen extent -3.3,-2.5 0.9,2.5, body extent -3,-2.45 3,2.45, height 1.63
